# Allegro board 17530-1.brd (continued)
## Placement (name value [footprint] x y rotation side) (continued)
R6311  10KR2J-3-GP  [R402H16]  45.16 227.18 0 top
R6312  10KR2J-3-GP  [R402H16]  46.25 227.18 0 top
R6313  10KR2J-3-GP  [R402H16]  37.19 243.31 0 top
R6314  10KR2J-3-GP  [R402H16]  33.91 248.49 90 top
R6315  75KR2F-GP  [R402H16]  33.88 247.45 270 top
R6321  0R2J-2-GP  [R402H16]  62.84 230.4 270 top
R6402  10KR2J-3-GP  [R402H16]  150.82 144.07 90 top
R6403  10KR2J-3-GP  [R402H16]  171.63 135.51 270 top
R6404  10KR2J-3-GP  [R402H16]  171.63 136.52 270 top
R6406  10KR2J-3-GP  [R402H16]  150.82 142.98 270 top
R6407  10KR2J-3-GP  [R402H16]  171.33 134.01 0 top
R6408  10KR2J-3-GP  [R402H16]  170.31 134.01 0 top
R6409  220R6J-1-GP  [R1206H28]  9.22 233.3 90 top
R6410  4K7R2J-2-GP  [R402H16]  5.99 225.15 90 top
R6411  10KR2J-3-GP  [R402H16]  7.9 225.15 270 top
R6412  4K7R2J-2-GP  [R402H16]  5.89 231.67 90 top
R6413  330R6J-1-GP  [R1206H28]  9.22 231.09 90 top
R6414  10KR2J-3-GP  [R402H16]  5.87 230.56 270 top
R6415  10KR2J-3-GP  [R402H16]  164.41 154.15 0 top
R6416  10KR2J-3-GP  [R402H16]  27.56 260.6 90 top
R6417  4K7R2J-2-GP  [R402H16]  20.65 239.98 270 top
R6418  360R3-GP  [R603H22]  31.32 258.75 180 top
R6419  1KR2J-1-GP  [R402H16]  17.96 238.48 0 top
R6420  33R2J-2-GP  [R402H16]  19.02 238.48 180 top
R6421  10KR2J-3-GP  [R402H16]  25.07 258.52 0 top
R6801  0R2J-2-GP  [R402H16]  184.86 6.53 0 top
R6802  0R2J-2-GP  [R402H16]  184.94 4.62 0 top
R9101  0R3J-0-U-GP  [R603H22]  157.99 171.83 90 top
R9104  0R3J-0-U-GP  [R603H22]  158.75 168.53 180 top
R9105  33R2J-2-GP  [R402H16]  164.87 177.24 90 top
R9106  33R2J-2-GP  [R402H16]  169.16 171.45 180 top
R9107  33R2J-2-GP  [R402H16]  167.08 171.45 180 top
R9108  0R2J-2-GP  [R402H16]  168.15 171.45 180 top
R9110  10KR2J-3-GP  [R402H16]  165.86 165.35 270 top
R9111  0R2J-2-GP  [R402H16]  165.66 163.75 180 top
R9112  0R0402-PAD-2-GP  [0R0402-PAD-1]  165.2 168.25 0 top
R9113  0R2J-2-GP  [R402H16]  166.42 159.13 90 top
R9403  0R0603-PAD-2-GP-U  [0R0603-PAD-1-U]  175.77 50.16 180 top
R9901  0R0402-PAD-2-GP  [0R0402-PAD-1]  121.59 63.45 270 top
R9902  0R0402-PAD-2-GP  [0R0402-PAD-1]  121.59 62.41 270 top
R9903  1KR2J-1-GP  [R402H16]  176.81 172.43 90 top
R9904  1KR2J-1-GP  [R402H16]  122.07 56.36 90 top
R9905  0R2J-2-GP  [R402H16]  181 167.26 90 top
R9906  1KR2J-1-GP  [R402H16]  127 54.23 270 top
R9907  1KR2J-1-GP  [R402H16]  124.08 55.24 90 top
R9908  1KR2J-1-GP  [R402H16]  127 55.37 270 top
R9909  2K2R2J-2-GP  [R402H16]  127.69 61.16 270 top
R9910  1KR2J-1-GP  [R402H16]  127.13 62.36 270 top
R9911  0R2J-2-GP  [R402H16]  127.69 60.02 270 top
R9912  150R2F-1-GP  [R402H16]  129.29 55.5 180 top
R9913  1KR2J-1-GP  [R402H16]  124.08 56.39 90 top
R9916  0R0402-PAD-2-GP  [0R0402-PAD-1]  159.41 8.64 0 top
R9917  0R0402-PAD-2-GP  [0R0402-PAD-1]  178.56 34.92 0 top
R9918  0R0402-PAD-2-GP  [0R0402-PAD-1]  158.37 8.64 0 top
R9919  0R0402-PAD-2-GP  [0R0402-PAD-1]  168.52 152.77 90 top
R9920  0R0402-PAD-2-GP  [0R0402-PAD-1]  185.19 12.7 0 top
R9921  0R0402-PAD-2-GP  [0R0402-PAD-1]  170.89 94.13 90 top
R9922  10KR2J-3-GP  [R402H16]  26.09 255.32 90 top
R9923  2K2R2J-2-GP  [R402H16]  180.97 164.01 270 top
R9924  0R2J-2-GP  [R402H16]  34.57 171.75 90 top
R9928  10KR2J-3-GP  [R402H16]  164.11 150.62 180 top
R9929  0R2J-2-GP  [R402H16]  11.11 26.87 90 top
R9930  0R2J-2-GP  [R402H16]  18.38 8.64 270 top
R9931  680R2F-GP  [R402H16]  135.81 30.58 90 top
R9932  33R2J-2-GP  [R402H16]  169.78 109.85 315 top
R9933  22R2J-2-GP  [R402H16]  46.1 218.44 135 top
R9934  33R2J-2-GP  [R402H16]  170.68 111.68 315 top
R9935  22R2J-2-GP  [R402H16]  44.86 220.14 135 top
R9936  20KR2F-L-GP  [R402H16]  170.81 115.44 90 top
R9937  20KR2F-L-GP  [R402H16]  170.52 108.5 225 top
R9938  0R2J-2-GP  [R402H16]  35.31 221.36 180 bottom
R9939  0R2J-2-GP  [R402H16]  41.15 226.95 180 bottom
RJ45R1  SKT-RJ45-USB-87-GP  [RUA1JA-KJKC-DE0-0R]  109 19.62 0 top
RN1901  SRN10KJ-6-GP  [ARES8-CN24-MUH20]  160.83 150.19 180 top
RN2001  SRN10KJ-5-GP  [ARES2H18]  168.85 136.57 270 top
RN2401  SRN8K2J-4-GP  [ARES8-CN24H20]  162.43 34.47 0 top
RN2402  SRN8K2J-4-GP  [ARES8-CN24H20]  157.05 29.39 90 top
RN2403  SRN8K2J-4-GP  [ARES8-CN24H20]  157.3 23.27 90 top
RN2404  SRN1KJ-7-GP  [SMD-ARES4H18]  169.58 34.6 0 top
RN2405  SRN1KJ-7-GP  [SMD-ARES4H18]  167.58 34.6 0 top
RN2501  SRN33J-5-GP-U  [SMD-ARES4H18]  166.02 157.29 270 top
RN2502  SRN33J-5-GP-U  [SMD-ARES4H18]  176.13 170.79 90 top
RN5601  SRN2K2J-1-GP  [ARES2H16]  68.45 24.26 180 top
RN5901  SRN2K2J-1-GP  [ARES2H16]  45.85 20.75 270 top
SATA1  SKT-SATA7P-168-GP  [LE18077-Z55D-4F]  111.5 200.4 180 top
SATA2  SKT-SATA7P-29-GP-U  [ABA-SAT-010-K04-U]  176.5 178 180 top
SATA3  SKT-SATA7P-169-GP  [LE18077-Z55D-4F]  131.5 200.4 180 top
SATAP1  PIN-CONN6B-S1-GP  [733-71-06TB18]  94 201.65 0 top
SB1  CANON-LAKE-GP  [BGA874M250240H60]  152.3 123.5 90 top
SD1  SKT-SDCARD-61-GP  [WK21921-151146-7H]  41.97 272.3 180 top
SLOT1  PCISLT36-7-GP  [AAA-PCI-003-K45]  162.4 56.59 90 top
SLOT2  PCISLT164-95-GP  [2EGH8211-27DL-4F]  182.8 56.44 270 top
SSKT1  SKT-91960-0084L-GP  [SKT-SOIC8-1H211]  173.33 162.08 180 top
SSKT2  SKT-SPI16P-7-GP  [SKT-SOIC16-153139H258]  173.61 161.59 90 top
TC1101  E820U2D5VM-6-GP  [ECAP-100D6D3H375]  69.98 138.68 180 top
TC3201  E220U16VM-L8-GP  [ECAP-100D6D3H493]  124.33 9.78 180 top
TC3801  E220U16VM-L8-GP  [ECAP-100D6D3H493]  91.74 265.43 270 top
TC3901  E220U16VM-L8-GP  [ECAP-100D6D3H493]  87.63 20.83 270 top
TP401  TPAD28-2-GP  [TPAD28]  81.74 85.47 180 bottom
TP402  TPAD28-2-GP  [TPAD28]  82.91 86.57 180 bottom
TP403  TPAD28-2-GP  [TPAD28]  85.29 83.08 180 bottom
TP404  TPAD28-2-GP  [TPAD28]  80.97 77.89 180 bottom
TP405  TPAD28-2-GP  [TPAD28]  80.87 79.88 180 bottom
TP406  TPAD28-2-GP  [TPAD28]  80.67 82.07 180 bottom
TP407  TPAD28-2-GP  [TPAD28]  120.07 54.76 0 top
TP408  TPAD28-2-GP  [TPAD28]  78.47 79.4 180 bottom
TP409  TPAD28-2-GP  [TPAD28]  74.55 83.08 180 bottom
TP410  TPAD28-2-GP  [TPAD28]  76.76 79.78 180 bottom
TP411  TPAD28-2-GP  [TPAD28]  80.72 86.41 180 bottom
TP412  TPAD28-2-GP  [TPAD28]  79.28 78.26 180 bottom
TP413  TPAD28-2-GP  [TPAD28]  79.02 86.51 180 bottom
TP414  TPAD28-2-GP  [TPAD28]  76.96 82.17 180 bottom
TP415  TPAD28-2-GP  [TPAD28]  76.83 78.28 180 bottom
TP416  TPAD28-2-GP  [TPAD28]  77.6 87.2 180 bottom
TP417  TPAD28-2-GP  [TPAD28]  81.66 75.26 180 bottom
TP418  TPAD28-2-GP  [TPAD28]  80.67 76.23 180 bottom
TP419  TPAD28-2-GP  [TPAD28]  83.31 74.68 180 bottom
TP420  TPAD28-2-GP  [TPAD28]  82.83 75.97 180 bottom
TP421  TPAD28-2-GP  [TPAD28]  78.38 77.24 180 bottom
TP422  TPAD28-2-GP  [TPAD28]  79.22 76.12 180 bottom
TP601  TPAD28-2-GP  [TPAD28]  54.23 98.93 180 bottom
TP701  TPAD28-2-GP  [TPAD28]  82.55 80.26 180 bottom
TP903  TPAD28-2-GP  [TPAD28]  88.24 89.26 180 bottom
TP1501  TPAD28-2-GP  [TPAD28]  156.82 128.78 180 bottom
TP1504  TPAD28-2-GP  [TPAD28]  162.77 123.29 180 bottom
TP1505  TPAD28-2-GP  [TPAD28]  163.27 122.17 180 bottom
TP1506  TPAD28-2-GP  [TPAD28]  156.34 138.68 0 top
TP1507  TPAD28-2-GP  [TPAD28]  163.15 125.7 180 bottom
TP1508  TPAD28-2-GP  [TPAD28]  166.95 126.72 0 top
TP1509  TPAD28-2-GP  [TPAD28]  168.94 111.46 0 top
TP2001  TPAD28-2-GP  [TPAD28]  167.26 132.79 0 top
TP2002  TPAD28-2-GP  [TPAD28]  154.53 25.12 0 top
TP2003  TPAD28-2-GP  [TPAD28]  162.76 131.62 180 bottom
TP2101  TPAD28-2-GP  [TPAD28]  150.11 138.68 0 top
TP2102  TPAD28-2-GP  [TPAD28]  149.99 139.95 0 top
TP2501  TPAD28-2-GP  [TPAD28]  46.25 260.15 0 top
TP2502  TPAD28-2-GP  [TPAD28]  47.75 260.12 0 top
TP3101  -  [TPAD30]  124.49 32.36 0 top
TP3102  -  [TPAD30]  122.38 32.38 0 top
TP3103  -  [TPAD30]  120.22 32.33 0 top
TP9106  -  [TPAD30]  157.61 176.28 0 bottom
TP9901  TPAD28-2-GP  [TPAD28]  159.56 6.35 0 top
TP9902  TPAD28-2-GP  [TPAD28]  178.54 33.15 0 top
TP9903  TPAD28-2-GP  [TPAD28]  158.37 6.65 0 top
TP9904  TPAD28-2-GP  [TPAD28]  168.83 152.65 90 bottom
TP9905  TPAD28-2-GP  [TPAD28]  185.7 11.13 0 top
TP9906  TPAD28-2-GP  [TPAD28]  170.69 92.58 90 top
TR3201  FILTER-4P-156-GP-U  [L125100-4PH24]  127.29 32.15 90 top
TR3202  FILTER-4P-156-GP-U  [L125100-4PH24]  127.29 29.07 90 top
TR3801  FILTER-4P-156-GP-U  [L125100-4PH24]  94.98 261.36 315 top
TR3802  FILTER-4P-156-GP-U  [L125100-4PH24]  96.59 259.75 315 top
TR3901  FILTER-4P-156-GP-U  [L125100-4PH24]  95.01 23.81 180 top
TR3902  FILTER-4P-156-GP-U  [L125100-4PH24]  92.85 23.79 180 top
TR5601  FILTER-4P-156-GP-U  [L125100-4PH24]  78.61 19.43 0 top
TR5602  FILTER-4P-156-GP-U  [L125100-4PH24]  76.45 19.43 0 top
TR5603  FILTER-4P-156-GP-U  [L125100-4PH24]  74.17 19.43 0 top
TR5604  FILTER-4P-156-GP-U  [L125100-4PH24]  71.88 19.43 0 top
U401  MMDT3904-2-GP  [SOT-363-1H44]  20.95 173.23 0 top
U2401  SCH5553-NU-GP  [PFPCC128-5H48]  170.89 22.38 180 top
U2405  TC7SZ32FU-2-GP  [SC70-5H44]  32 172.52 0 top
U2501  MX25L25673GM2I-08G-GP  [SOIC8-1H86]  173.33 162.08 0 top
U2502  MX25L25673GMI-10G-GP  [SOIC16-6H105]  173.61 161.59 270 top
U2601  G709T1UF-GP  [SOT-23-5H56]  179.55 6.58 0 top
U2602  SNLVC1G08DCKRG4-GP  [SC70-5H44]  176.1 6.96 0 top
U2701  ALC3820-CG-GP  [LQFP48H63]  66.42 258.83 180 top
U3101  RTL8111G-CGT-1-GP-U2  [QFN32J4-G2D85H36]  138.05 24 90 top
U3201  G524B1T11U-GP  [SOT-23-5H58]  126.72 16.03 0 top
U3301  RTS5170-GR-GP  [QFN24-G2D5H40-U]  38.73 259.08 180 top
U3801  G524B1T11U-GP  [SOT-23-5H58]  86.87 260.1 180 top
U3901  G524B1T11U-GP  [SOT-23-5H58]  89.13 28.07 0 top
U4002  2N7002KDW-1-GP  [SOT-363H44]  100.58 28.7 90 top
U4003  2N7002K-2-GP  [SOT23DGS2D4H44]  104.27 30.23 0 top
U4009  SNLVC1G08DCKRG4-GP  [SC70-5H44]  112.39 33.53 270 top
U4010  SNLVC1G08DCKRG4-GP  [SC70-5H44]  26.8 172.97 180 top
U4201  AOZ2331DI-1-GP  [SON14J3020-G2610H32]  6.96 219.33 0 top
U4202  2N7002KDW-1-GP  [SOT-363H44]  44.53 193.32 90 top
U4204  TPCC8103-GP  [PPAK-8P-3333-2H36]  183.9 193.68 0 top
U4801  2N7002KDW-1-GP  [SOT-363H44]  154.89 189.87 0 top
U5601  2N7002KDW-1-GP  [SOT-363H44]  68.83 20.6 0 top
U5602  AP2331SA-7-GP  [SOT23-2D4-312H48]  65.02 24.79 0 top
U5901  RTD2166-CGT-GP  [QFN32J4-G2D85H36]  56.39 19.56 270 top
U6301  RT9724GB-GP  [SOT-23-5H51]  36.98 233.09 0 top
U6302  2N7002K-2-GP  [SOT23DGS2D4H44]  34.82 245.03 0 top
U6303  2N7002K-2-GP  [SOT23DGS2D4H44]  67.06 233.81 90 top
U6401  2N7002KDW-1-GP  [SOT-363H44]  28.07 263.27 180 top
U6402  2N7002KDW-1-GP  [SOT-363H44]  27.23 257.76 0 top
U9101  NPCT750JAAYX-GP  [QFN32G5-G3D6H32]  162.94 173.1 90 top
UC3201  SCD01U50V2KX-1DLGP  [C402H22]  122.33 16.41 0 top
UC3202  SCD1U16V2KX-3DLGP  [C402H22]  123.22 16.41 0 top
UC3203  SCD1U16V2KX-3DLGP  [C402H22]  124.18 15.39 180 top
UC3801  SCD1U16V2KX-3DLGP  [C402H22]  87.38 262.89 270 top
UC3901  SCD1U16V2KX-3DLGP  [C402H22]  88.6 25.32 90 top
USB2R1  SKT-USB12-24-GP  [SKT-USB12-157183]  88 9.19 0 top
USB3F1  SKT-USB11-153-GP  [SKT-USB11-138166]  85.22 274.75 180 top
USB3F2  SKT-USB11-153-GP  [SKT-USB11-138166]  107.22 274.75 180 top
VGA1  D-SUB-15-295-GP  [VDS075W-D307-00A3F2B]  37 3.9 0 top
X1801  XTAL-24MHZ-182-GP  [OSC-3225-4P-3H36]  147.07 102.82 270 top
X1802  XTAL-32D768KHZ-88-GP  [SMD49-3215-0713H36]  169.8 149.22 0 top
X3101  XTAL-25MHZ-202-GP  [SMD-OSC38H20]  137.67 32.59 180 top

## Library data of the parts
ATX1 = W4202VT-203P-D: tolerance: 020.80369.0006
ATX2 = HM3502E-P1: tolerance: 20.81163.004
AUD1 = ABA-JAK-028-K03: tolerance: 22.10251.831
BT2501 = 20-00950-1A01-A-U: tolerance: 022.70019.0001
C402 C403 C803 C806 C1103 C1104 C1108 = C402H22: tolerance: 78.10421.L0L
C601 C603 C805 C807 C808 C1101 C1102 C1105 C1106 C1109 C1201 C1202 C1205-C1208 C1210 C1212 C2101 C2102 C2104-C2107 C2113-C2117 C2406 C2408 C2415-C2423 C2425 C2704 C2707 C2708 C2712 C2714 C2716-C2718 C2721 C3101 C3103 C3105-C3108 C3111 C3113 C3301 C3307 C3806 C3807 C4007 C4008 C4010 C4011 C4212 C4218 C4220 C4222 C4225 C4301 C4302 C5101 C5902-C5906 C5908-C5915 C6203 C6205 C6213 C6215 C6301-C6304 C6309 C6310 C6402 C6403 C9102 C9103 C9105 C9106 C9310-C9312 C9403-C9405 C9410 C9901-C9905 C9907-C9911 PC4803 PC4810 PC4913 PC5205 UC3202 UC3203 UC3801 UC3901 = C402H22: tolerance: 78.10421.2FLDL
C602 C1209 = C402H22: tolerance: 78.22321.2FLDL
C801 C1033 C1203 C2006 C2007 C2103 C2110 C2120-C2125 C2128 C2405 C2412 C2501 C3112 C3201 C3303 C3304 C3805 C3901 C4009 C4012 C4013 C4203 C4204 C4224 C4226 C4227 C6201 C6404 = C402H22: tolerance: 78.10523.5FLDL
C802 C4209 C4210 C5609 PC4407 PC4408 PC4410 PC4412 PC4420 PC4421 PC4428 PC4429 = C402H22: tolerance: 78.10422.5FLDL
C804 C2703 C2705 C2709-C2711 C2901 C3001 C3002 C3007 C3008 C4208 C6013 C6014 C6206 C6214 PC4501 PC4502 PC4506 PC4507 PC4511 PC4512 PC4516 PC4517 PC4601 PC4602 PC4606 PC4607 PC4702 PC4703 PC4901-PC4905 PC5004-PC5007 PC5102-PC5105 = C805H58: tolerance: 78.10622.51LDL
C1025-C1027 PC1004-PC1006 PC1019-PC1023 = C805H58: tolerance: 78.22610.L2L
C1028-C1031 PC1050-PC1053 = C805H54: tolerance: 78.47610.51LDL
C1032 C2722 PC1007-PC1012 PC1018 PC1034-PC1045 PC1058 PC4808 PC4809 = C805H54: tolerance: 78.22610.51LDL
C1107 C1204 C1211 C2108 C2109 C2411 C2414 C3102 C3104 C3114 C3302 C5907 = C603H36: tolerance: 78.47520.5BLDL
C1110 C1213 = C402H22: tolerance: 78.22510.5FLDL
C1801-C1804 = C402H22: tolerance: 78.15034.1FLDL
C2111 C2112 C2118 C2119 C2127 C2129 C6308 PC1001 PC1002 PC1046-PC1049 = C603H40: tolerance: 78.22610.5BLDL
C2126 C2424 C2706 C2713 C3117 C3306 C4205 C4206 C6307 C9101 C9104 C9411 = C603H36: tolerance: 78.10610.5BLDL
C2401 C2403 C2413 C2427 C2903 C2906 C2907 C3003-C3006 C3009 C3010 = C402H22: tolerance: 78.10134.1FLDL
C2402 C2404 PC4405 PC4418 PC4812 = C402H22: tolerance: 78.22224.2FLDL
C2407 C2426 PC4403 PC4806 UC3201 = C402H22: tolerance: 78.10324.2FLDL
C2701 C2702 C5901 PC4402 = C603H36: tolerance: 78.22523.5BLDL
C2715 C5916-C5921 PC4914 PC4915 = C402H22: tolerance: 78.22034.1FLDL
C2719 C2720 PC4503 PC4508 PC4513 PC4518 PC4603 PC4608 PC4704 PC4906-PC4908 PC5008 PC5106 = C603H35: tolerance: 78.10424.2BLDL
C2902 C4207 C4211 = C805H56: tolerance: 78.10622.LAL
C2904 C2905 = C805H54: tolerance: 78.47522.51LDL
C3109 = C402H22: tolerance: 78.10421.2FLDL; signal model: Graser_C3109
C3110 = C402H22: tolerance: 78.10421.2FLDL; signal model: Graser_C3110
C3115 = C402H22: tolerance: 78.10421.2FLDL; signal model: Graser_C3115
C3116 = C402H22: tolerance: 78.10421.2FLDL; signal model: Graser_C3116
C3118 C3119 = C402H22: tolerance: 78.20034.1FLDL
C3305 = C402H22: tolerance: 78.6R874.1FLDL
C3801 = C402H22: tolerance: 78.10421.2FLDL; signal model: Graser_C3801
C3802 = C402H22: tolerance: 78.10421.2FLDL; signal model: Graser_C3802
C3803 = C402H22: tolerance: 78.10421.2FLDL; signal model: Graser_C3803
C3804 = C402H22: tolerance: 78.10421.2FLDL; signal model: Graser_C3804
C4201 C4202 PC4409 PC4416 PC4422 PC4427 PC4807 PC4911 PC4912 = C402H22: tolerance: 78.10224.2FLDL
C4219 = C402H22: tolerance: 78.10324.L0L
C4221 C4223 = C603H40: tolerance: 078.22522.05BD
C4303 C4304 PC4401 PC4504 PC4509 PC4514 PC4519 PC4604 PC4609 PC4701 PC4705 PC4706 PC4804 PC4909 PC4910 PC4916 PC4917 PC5001-PC5003 PC5010 PC5101 PC5107 PC5109 PC5202 = C603H36: tolerance: 078.10524.05BD
C5601 = C402H22: tolerance: 78.10421.2FLDL; signal model: Graser_C5601
C5602 = C402H22: tolerance: 78.10421.2FLDL; signal model: Graser_C5602
C5603 = C402H22: tolerance: 78.10421.2FLDL; signal model: Graser_C5603
C5604 = C402H22: tolerance: 78.10421.2FLDL; signal model: Graser_C5604
C5605 = C402H22: tolerance: 78.10421.2FLDL; signal model: Graser_C5605
C5606 = C402H22: tolerance: 78.10421.2FLDL; signal model: Graser_C5606
C5607 = C402H22: tolerance: 78.10421.2FLDL; signal model: Graser_C5607
C5608 = C402H22: tolerance: 78.10421.2FLDL; signal model: Graser_C5608
C5610 C5611 PC4404 PC4414 PC4417 PC4426 = C402H22: tolerance: 78.47124.2FLDL
C5922 C5923 = C402H22: tolerance: 078.2R074.01FD
C6001 = C402H22: tolerance: 78.10324.2FLDL; signal model: Graser_C6001
C6002 = C402H22: tolerance: 78.10324.2FLDL; signal model: Graser_C6002
C6003 = C402H22: tolerance: 78.10324.2FLDL; signal model: Graser_C6003
C6004 = C402H22: tolerance: 78.10324.2FLDL; signal model: Graser_C6004
C6005 = C402H22: tolerance: 78.10324.2FLDL; signal model: Graser_C6005
C6006 = C402H22: tolerance: 78.10324.2FLDL; signal model: Graser_C6006
C6007 = C402H22: tolerance: 78.10324.2FLDL; signal model: Graser_C6007
C6008 = C402H22: tolerance: 78.10324.2FLDL; signal model: Graser_C6008
C6009 = C402H22: tolerance: 78.10324.2FLDL; signal model: Graser_C6009
C6010 = C402H22: tolerance: 78.10324.2FLDL; signal model: Graser_C6010
C6011 = C402H22: tolerance: 78.10324.2FLDL; signal model: Graser_C6011
C6012 = C402H22: tolerance: 78.10324.2FLDL; signal model: Graser_C6012
C6209 = C402H22: tolerance: 078.22423.05FD; signal model: Graser_C6209
C6210 = C402H22: tolerance: 078.22423.05FD; signal model: Graser_C6210
C6211 = C402H22: tolerance: 078.22423.05FD; signal model: Graser_C6211
C6212 = C402H22: tolerance: 078.22423.05FD; signal model: Graser_C6212
C6305 = C402H22: tolerance: 78.10421.2FLDL; signal model: Graser_C6305
C6306 = C402H22: tolerance: 78.10421.2FLDL; signal model: Graser_C6306
C9301 = C402H22: tolerance: 078.22423.05FD; signal model: Graser_C9301
C9302 = C402H22: tolerance: 078.22423.05FD; signal model: Graser_C9302
C9303 = C402H22: tolerance: 078.22423.05FD; signal model: Graser_C9303
C9304 = C402H22: tolerance: 078.22423.05FD; signal model: Graser_C9304
C9305 = C402H22: tolerance: 078.22423.05FD; signal model: Graser_C9305
C9306 = C402H22: tolerance: 078.22423.05FD; signal model: Graser_C9306
C9307 = C402H22: tolerance: 078.22423.05FD; signal model: Graser_C9307
C9308 = C402H22: tolerance: 078.22423.05FD; signal model: Graser_C9308
C9309 = C402H22: tolerance: 078.22423.05FD; signal model: Graser_C9309
C9313 = C402H22: tolerance: 078.22423.05FD; signal model: Graser_C9313
C9314 = C402H22: tolerance: 078.22423.05FD; signal model: Graser_C9314
C9315 = C402H22: tolerance: 078.22423.05FD; signal model: Graser_C9315
C9316 = C402H22: tolerance: 078.22423.05FD; signal model: Graser_C9316
C9317 = C402H22: tolerance: 078.22423.05FD; signal model: Graser_C9317
C9318 = C402H22: tolerance: 078.22423.05FD; signal model: Graser_C9318
C9319 = C402H22: tolerance: 078.22423.05FD; signal model: Graser_C9319
C9320 = C402H22: tolerance: 078.22423.05FD; signal model: Graser_C9320
C9321 = C402H22: tolerance: 078.22423.05FD; signal model: Graser_C9321
C9322 = C402H22: tolerance: 078.22423.05FD; signal model: Graser_C9322
C9323 = C402H22: tolerance: 078.22423.05FD; signal model: Graser_C9323
C9324 = C402H22: tolerance: 078.22423.05FD; signal model: Graser_C9324
C9325 = C402H22: tolerance: 078.22423.05FD; signal model: Graser_C9325
C9326 = C402H22: tolerance: 078.22423.05FD; signal model: Graser_C9326
C9328 = C402H22: tolerance: 078.22423.05FD; signal model: Graser_C9328
C9329 = C402H22: tolerance: 078.22423.05FD; signal model: Graser_C9329
C9331 = C402H22: tolerance: 078.22423.05FD; signal model: Graser_C9331
C9332 = C402H22: tolerance: 078.22423.05FD; signal model: Graser_C9332
C9334 = C402H22: tolerance: 078.22423.05FD; signal model: Graser_C9334
C9335 = C402H22: tolerance: 078.22423.05FD; signal model: Graser_C9335
C9336 = C402H22: tolerance: 078.22423.05FD; signal model: Graser_C9336
C9337 = C402H22: tolerance: 078.22423.05FD; signal model: Graser_C9337
C9338 = C402H22: tolerance: 078.22423.05FD; signal model: Graser_C9338
C9401 = C402H22: tolerance: 078.22423.05FD; signal model: Graser_C9401
C9402 = C402H22: tolerance: 078.22423.05FD; signal model: Graser_C9402
CPU1 = SKTBGA1151R754612-UH369: tolerance: 062.10015.0161
D2501 D2601 D2602 D5601 D6301 D6302 = SOD323AKH38: tolerance: 83.R5003.H8H
D2502 = SOT-23-9H44: tolerance: 75.00054.A7D
D2701 = SOD-523-4H28: tolerance: 75.05125.070
D2901 = SOT23-2D4-123H44: tolerance: 075.00054.0A7D
D4301 D4302 = D5126145AKH91: tolerance: 83.P4SSM.EAM
DB2001 DB2002 R803 R2102 R6309 R9101 R9104 = R603H22: tolerance: 63.00000.00L
DIMM1 DIMM2 = AH08847-A9L2-4M: tolerance: 022.10010.0761
EU3201-EU3204 EU3803 EU3901 = SOT-6-1H58: tolerance: 075.00199.007C
EU3801 EU3802 EU5601-EU5603 = DFN10G2510H26: tolerance: 75.01045.073
EU5901 EU5902 = SOT-6H58: tolerance: 075.02304.0C7C
F3301 = POLYSW-2114H30: tolerance: 069.50001.0031
F5901 = POLYSW-2114H30: tolerance: 69.48001.081
FANC1 = P254-1104A0ADKP-W: tolerance: 021.60305.0104
FANS1 = HF2704F-RM1: tolerance: 021.60234.0104
FL2901-FL2903 L3001-L3006 = L402H24: tolerance: 68.00213.031
HDMI1 = SKT-HDMI23-150122-9-U: tolerance: 62.10078.641
HPMIC1 = C35012W-L101-39AA00R: tolerance: 022.10002.0A81
HS1901 HS1902 = HB9603E-DW: tolerance: 21.60564.102
HS2601 HS2604 = GEN330R190-8-F-C: tolerance: ZZ.AFEN8.190
HS2602 HS2603 HS2605 HS2606 = GEN315R158-8-F-C-S-U: tolerance: ZZ.SCREW.541
HS6301 = STF256R109H99: tolerance: 34.3NH01.001
JMP1 = 21S-92-03GB16: tolerance: 021.60308.0203
L2101 L2102 = L603H38: tolerance: 68.00230.131
L2701-L2703 = L603H38: tolerance: 68.00335.181
L5901 L5902 = L603H38: tolerance: 68.00335.101
L5903-L5905 = L1608-UH38: tolerance: 68.00084.B61
LED1 = LED1608AKH28: tolerance: 83.19213.H70
LPC1 = 87212-1400N: tolerance: 20.F0765.014
NGFF1 = AS0BC21-S40BE-7H: tolerance: 062.10003.0611
NGFF2 = AS0BC21-S85BM-7H: tolerance: 062.10003.0601
PC4406 PC4419 = C402H22: tolerance: 78.33034.1FLDL
PC4411 PC4423 = C402H22: tolerance: 78.33224.2FLDL
PC4413 = C402H22: tolerance: 78.22124.2FLDL
PC4415 PC4425 PC4505 PC4510 PC4515 PC4520 PC4605 PC4610 PC4707 PC5014 PC5110 = C402H22: tolerance: 78.15224.2FLDL
PC4424 = C402H22: tolerance: 78.33124.2FLDL
PC4708 PC5013 PC5108 = C402H22: tolerance: 78.18034.1FLDL
PC4801 PC4802 PC5009 PC5011 PC5012 PC5201 PC5203 PC5204 = C805H50: tolerance: 78.10623.51LDL
PC4805 PC4811 PC5015 = C402H22: tolerance: 078.47322.02FD
PC4918 PC4919 = C402H22: tolerance: 078.22423.05FD
PC5206 = C402H22: tolerance: 78.15134.1FL
PG4501-PG4508 PG4601-PG4604 PG4701 PG4901 PG4902 PG5005 PG5006 PR4701-PR4706 PR4801-PR4807 PR4809 PR4901-PR4906 PR4908 PR4910 PR4912 PR4914 PR4916 PR4918 PR4920 PR4922 PR4924 PR4925 PR4927 PR4929 PR4933 PR4934 PR4936-PR4940 PR4945-PR4949 PR5006 PR5008 PR5010-PR5013 PR5015 PR5017 PR5018 PR5020-PR5023 PR5026-PR5030 PR5117-PR5135 = GAP-CLOSE-PWR-3: tolerance: ZZ.CLOSE.001
PG4903 = GAP-CLOSE-PWR-2U: tolerance: ZZ.0TPAD.011
PL4501-PL4504 PL4601 PL4602 = RT-D6D3-1D4-103065H394: tolerance: 019.40016.0211
PL4701 = L7066-1830-UH119: tolerance: 68.R4710.10M
PL4901 PL4902 = RT-D6D6-6D6-108108H426: tolerance: 019.40027.0011
PL4903-PL4905 PL5002 PL5003 PL5104 PL5105 = L805H44: tolerance: 68.00335.111
PL5001 = RT-D6D4-1D9-103072H394: tolerance: 019.40016.0191
PL5101 = L115100-2030H158: tolerance: 68.1R51A.10E
PR4401 = R603H22: tolerance: 64.2R205.55L
PR4402 PR4409 PR4442 R404 R1103 R1106 R1203 R1206 R3103 = R402H16: tolerance: 64.10015.6DL
PR4403 = R402H16: tolerance: 64.26125.6DL
PR4404 PR4416 PR4423 PR4445 PR4454 R402 R403 R1513 R2024 R2605 R2614 = R402H14: tolerance: 64.10005.6DL
PR4405 = R402H16: tolerance: 64.45R35.6DL
PR4406 R3001 R3002 R3005 R3006 R3013 R3014 R5913-R5915 = R402H16: tolerance: 64.75R05.6DL
PR4407 PR4439 R5916 R5917 = R402H16: tolerance: 64.47R05.6DL
PR4408 PR4440 = R402H16: tolerance: 64.40215.6DL
PR4410 PR4435-PR4438 PR4459 PR4460 PR4715 PR4717 PR4808 PR4813 PR4815 R2905 R2906 = R402H14: tolerance: 64.10R05.6DL
PR4411 R418 R802 = R402H16: tolerance: 64.49R95.6DL
PR4412 PR4415 PR4419 PR4422 PR4426 PR4427 PR4429 PR4432 PR4434 PR4443 PR4446 PR4451 PR4960 R2706 R2707 R2709 R2711 = R402H16: tolerance: 64.10035.6DL
PR4413 PR4424 PR4441 PR4716 PR4956 PR4957 PR5116 PR5202 PR5206 R2411 R2413 R5918 = R402H16: tolerance: 64.10025.6DL
PR4414 PR4417 PR4421 PR4425 PR4444 PR4448 = R402H16: tolerance: 64.69815.6DL
PR4418 PR4447 PR4812 PR5019 PR5204 R407 R408 R410-R412 R417 R801 R809 R902 R903 R1105 R1205 R1701 R1702 R1816 R1818 R1822 R2034 R2036 R2039 R2422 R2426 R2434 R2438 R2439 R3102 R3813 R4006-R4010 R4013 R4015 R4019 R4021 R4024 R4025 R4201 R4202 R4302 R5003 R5101 R5911 R5912 R6201 R9112 R9901 R9902 R9916-R9921 = 0R0402-PAD-1: tolerance: ZZ.00PAD.M11
PR4420 = R402H16: tolerance: 64.30015.6DL
PR4428 = R402H16: tolerance: 64.27035.6DL
PR4430 R2403 R2405 R2412 R2465 R2469 R2470 R2473 = R402H16: tolerance: 64.30025.6DL
PR4431 PR4455 PR4466 PR4468 = NTC-402H24-U: tolerance: 69.60028.041
PR4433 = R402H16: tolerance: 64.35725.6DL
PR4449 PR4453 = R603: tolerance: 64.68125.55L
PR4450 = R402H16: tolerance: 64.36015.6DL
PR4452 = R402H16: tolerance: 64.26135.6DL
PR4456 = R402H16: tolerance: 64.13335.6DL
PR4457 = R402H16: tolerance: 64.24925.6DL
PR4458 = R402H16: tolerance: 64.42225.6DL
PR4461 = R402H16: tolerance: 64.75R05.6DL; signal model: Graser_PR4461
PR4462 R2415 R2416 = R402H16: tolerance: 64.20015.6DL
PR4463 PR4464 R2009 R2010 = R402H16: tolerance: 64.49905.6DL
PR4465 = R402H16: tolerance: 64.47525.6DL
PR4467 PR4469 = R402H16: tolerance: 64.38325.6DL
PR4471 PR5025 R2466 R5609 R9936 R9937 = R402H16: tolerance: 64.20025.6DL
PR4501 PR4505 PR4507 PR4511 PR4514 PR4517 PR4520 PR4523 PR4525-PR4528 PR4601 PR4605 PR4608 PR4611 PR4613 PR4614 = R805H24: tolerance: 64.2R205.16L
PR4503 PR4509 PR4515 PR4521 PR4603 PR4609 PR4710 PR4959 PR4961 PR5004 PR5107 PR5109 R413 R416 R422 R805 R1502 R1506 R1509 R1510 R1601 R1604-R1607 R1610 R1704-R1706 R1709 R1712-R1714 R1801 R1803 R1805-R1807 R1809 R1902 R1905 R1910-R1912 R1917-R1919 R2001 R2002 R2007 R2015 R2041 R2044 R2303 R2305 R2312 R2314 R2419 R2421 R2425 R2427 R2430 R2432 R2435 R2448 R2449 R2452 R2453 R2462-R2464 R2476-R2478 R2701 R2716 R2717 R3811 R3812 R3814 R3815 R3817 R4001 R4020 R4022 R4204 R4207 R4220 R4222 R4801 R4803 R6304 R6306 R6308 R6311-R6314 R6402-R6404 R6406-R6408 R6411 R6414-R6416 R6421 R9110 R9922 R9928 = R402H16: tolerance: 63.10334.1DL
PR4504 PR4510 PR4516 PR4522 PR4604 PR4610 = R805H24: tolerance: 63.1R031.16L
PR4506 PR4512 PR4518 PR4524 PR4606 PR4612 R415 R427 R2011 R2026 R2028 = R402H16: tolerance: 64.51R05.6DL
PR4707 PR4709 PR4712 PR4713 PR4932 PR4941-PR4944 PR4950 PR4951 PR5005 PR5007 PR5016 PR5108 PR5110 PR5113 PR5115 = R805H24: tolerance: 63.2R231.16L
PR4708 = R402H16: tolerance: 64.40225.6DL
PR4711 PR5112 = R402H16: tolerance: 64.47035.6DL
PR4714 PR5114 = R402H16: tolerance: 64.48715.6DL
PR4810 = R805H24: tolerance: 63.10133.16L
PR4811 = R402H16: tolerance: 64.22015.6DL
PR4814 = R402H16: tolerance: 64.47015.6DL
PR4816 = R402H16: tolerance: 64.24025.6DL
PR4952 = R402H16: tolerance: 64.78725.6DL
PR4953 = R402H16: tolerance: 64.62025.6DL
PR4954 = R402H16: tolerance: 64.66515.6DL
PR4955 = R402H16: tolerance: 64.15425.6DL
PR4958 R414 R806 R807 R810 R1515 R1516 R2045-R2048 R2052-R2055 R2406 R2410 R2467 R2475 R2619 R4206 R5910 R5919 = R402H16: tolerance: 63.10434.1DL
PR4962 = R402H16: tolerance: 64.28025.6DL
PR5001 = R402H16: tolerance: 64.2R205.6DL
PR5002 R2101 R2503 R2705 R2708 R3105 R9403 = 0R0603-PAD-1-U: tolerance: ZZ.00PAD.M21
PR5003 = R402H16: tolerance: 64.20535.6DL
PR5009 = R402H16: tolerance: 64.62035.6DL
PR5014 PR5201 PR5203 = 0R0805-PAD-1-U: tolerance: ZZ.00PAD.M31
PR5024 = R402H16: tolerance: 64.15825.6DL
PR5111 = R402H16: tolerance: 64.56025.6DL
PR5205 = R402H16: tolerance: 64.21525.6DL
PT4501 PT4504 PT4506 PT4601 PT4901 = ECAP-138D8-UH355: tolerance: 09.2771D.C8L
PT4502 PT4503 PT4505 PT4507 PT4508 PT4602-PT4605 PT4701 PT4702 PT4801 PT5001 PT5101 TC1101 = ECAP-100D6D3H375: tolerance: 09.8271V.08L
PT4902 PT4903 = SE3116H241: tolerance: 79.22710.30L
PU4401 = QFN52J6-G4D8-UH40: tolerance: 074.81220.0D73
PU4501 PU4505 PU4509 PU4513 PU4601 PU4604 PU4802 PU4901 PU4903 PU5002 Q4201 = PPAK-8P-5262H40: tolerance: 084.36358.0037
PU4502 PU4506 PU4510 PU4514 PU4602 PU4605 = DFN8G2-G1309-UH40: tolerance: 074.81258.00E3
PU4503 PU4504 PU4507 PU4508 PU4511 PU4512 PU4515 PU4516 PU4603 PU4606 PU4904 PU4905 PU5003 = PPAK-8P-5262H40: tolerance: 084.36356.0037
PU4701 PU5101 = DFN10G3-G265175H32: tolerance: 74.08237.B73
PU4702 PU5102 = PPAK-8P-G5324H44-COLAY: tolerance: ZZ.00215.037
PU4801 = SOT-6H58: tolerance: 74.05611.03P
PU4902 = QFN20-G1D75H32: tolerance: 074.06575.0A43
PU5001 = QFN20-G1D75H32: tolerance: 074.08231.0073
PU5201 = SOIC8-G3530H63: tolerance: 74.05930.B3D
PWRSW1 = A2003WV0-2LX4PA-6T-Z-U: tolerance: 21.62977.204
Q801 Q5901 = SOT23DGS2D8H50: tolerance: 84.03418.A31
Q802 Q5601 Q6401 Q9103 U4002 U4202 U4801 U5601 U6401 U6402 = SOT-363H44: tolerance: 75.27002.F7C
Q2001 Q2701-Q2704 = SOT23CBE2D4H44: tolerance: 84.T3906.E11
Q2401 Q2402 Q2405 Q2406 Q2408 Q2901 Q3001 Q4002 U401 = SOT-363-1H44: tolerance: 75.03904.D7C
Q2403 Q2404 Q2409 Q4205 Q4207 Q9102 = SOT23CBE2D4H44: tolerance: 84.T3904.H11
Q2407 Q9101 U4003 U6302 U6303 = SOT23DGS2D4H44: tolerance: 84.2N702.J31
Q3801 = SOT-363H44: tolerance: 75.03904.A7C
Q4206 = SOT23DGS2D4H48: tolerance: 84.02130.031
R301 R602 R701 R1207 = R402H16: tolerance: 64.24R95.6DL
R401 = R402H16: tolerance: 64.56R25.6DL
R405 = R402H16: tolerance: 64.22005.6DL
R409 = R402H16: tolerance: 64.49905.6DL; signal model: Graser_R409
R419 = R402H16: tolerance: 64.60415.6DL
R420 = R402H16: tolerance: 64.28015.6DL
R421 = R402H16: tolerance: 64.20R05.6DL; signal model: Graser_R421
R423 R2021 R2504 = R402H16: tolerance: 64.15015.6DL
R424-R426 R1611 R1703 R1708 R2003 R2012-R2014 R2037 R2038 R2318 R2325 R2450 R2501 R2502 R2506 R2718 R2719 R2902 R2908 R2910 R3008 R3010 R4023 R6419 R9903 R9904 R9906-R9908 R9910 R9913 = R402H16: tolerance: 63.10234.1DL
R601 R1204 = R402H16: tolerance: 64.2R005.6DL
R702 = R402H16: tolerance: 63.20034.1DL
R804 R1511 R2474 R2702 R4203 R4802 = R402H16: tolerance: 63.47334.1DL
R808 R2035 R2043 R2301 R2302 R2307 R2326 R2328 R2431 R2601 R2615 R2704 R2903 R2904 R3807 R3808 R4205 R4301 R5901-R5909 R6410 R6412 R6417 = R402H16: tolerance: 63.47234.1DL
R901 = R402H16: tolerance: 64.20R05.6DL; signal model: Graser_R901
R1101 R1201 = R402H16: tolerance: 64.24005.6DL
R1102 R1202 R2004 R2306 R2612 R2715 R3809 R3810 R3818 R5001 R5002 R6202 R6203 R6303 R6321 R6801 R6802 R9108 R9111 R9113 R9905 R9911 R9924 R9929 R9930 R9938 R9939 = R402H16: tolerance: 63.R0034.1DL
R1104 R5601-R5608 = R402H16: tolerance: 63.47134.1DL
R1503 R1508 R1901 R2402 R2604 R2617 R4017 R4018 = R402H16: tolerance: 64.82015.6DL
R1504 R1913 R2017 R2019 R2020 R2022 R2032 R2033 R2433 R2703 R6420 R9105-R9107 R9932 R9934 = R402H16: tolerance: 63.33034.1DL
R1507 R5610 = R402H16: tolerance: 63.10534.1DL
R1512 R9912 = R402H16: tolerance: 64.15005.6DL
R1514 = R402H16: tolerance: 64.20005.6DL
R1609 = R402H16: tolerance: 64.11305.6DL
R1710 = R402H16: tolerance: 64.61905.6DL; signal model: Graser_R1710
R1711 = R402H16: tolerance: 63.30034.1DL; signal model: Graser_R1711
R1802 = R402H16: tolerance: 64.60R45.6DL
R1812 R2710 R2712 = R402H16: tolerance: 64.20035.6DL
R1814 = R603H22: tolerance: 63.10633.15L
R1906-R1908 R2005 R2324 R2327 R2329 R2603 R2616 R2901 R3011 R3012 R9909 R9923 = R402H16: tolerance: 63.22234.1DL
R1914-R1916 R2401 R2407 R9933 R9935 = R402H16: tolerance: 63.22034.1DL
R2006 = 0R0402-PAD-1: tolerance: ZZ.00PAD.M11; signal model: Graser_R2006
R2025 R2027 = R402H16: tolerance: 63.30034.1DL
R2040 R2042 = R402H16: tolerance: 64.30125.6DL
R2201 = R402H16: tolerance: 64.30R15.6DL; signal model: Graser_R2201
R2304 R2309 R2310 R2313 R2317 R2323 R2442 R2602 R2618 R4003 = R402H16: tolerance: 63.20334.1DL
R2404 R2414 R2417 = R402H16: tolerance: 64.91015.6DL
R2408 R9931 = R402H16: tolerance: 64.68005.6DL
R2409 R2472 = R402H16: tolerance: 64.68015.6DL
R2423 = R402H16: tolerance: 64.71515.6DL
R2424 = R402H16: tolerance: 64.33025.6DL
R2428 = R402H16: tolerance: 64.43R25.6DL; signal model: Graser_R2428
R2429 = R402H16: tolerance: 64.16005.6DL
R2446 = R402H16: tolerance: 64.33035.6DL
R2458 = R402H16: tolerance: 63.75034.1DL; signal model: Graser_R2458
R2468 = R402H16: tolerance: 64.16025.6DL
R2471 = R402H16: tolerance: 64.16515.6DL
R2505 = R402H16: tolerance: 64.45325.6DL
R2507 = R402H16: tolerance: 63.33034.1DL; signal model: Graser_R2507
R2611 = R402H16: tolerance: 64.95315.6DL
R2613 = R402H16: tolerance: 64.10525.6DL
R2714 = R402H16: tolerance: 64.22035.6DL
R2907 R2909 R3003 R3004 R3007 R3009 R3015 R3016 R4005 R4011 = R402H16: tolerance: 63.22334.1DL
R3101 = R402H16: tolerance: 64.24915.6DL
R3104 = R603H22: tolerance: 64.10045.55L
R3106 = R402H16: tolerance: 64.15025.6DL
R3201 R3202 R4014 R4016 = R402H16: tolerance: 64.24905.6DL
R3203 = 0R1210-4P-PAD: tolerance: ZZ.00PAD.I21; signal model: Graser_R3203
R3204 = R603H22: tolerance: 63.51133.15L
R3205 = 0R1210-4P-PAD: tolerance: ZZ.00PAD.I21; signal model: Graser_R3205
R3206 = 0R1210-4P-PAD: tolerance: ZZ.00PAD.I21; signal model: Graser_R3206
R3207 = 0R1210-4P-PAD: tolerance: ZZ.00PAD.I21; signal model: Graser_R3207
R3301 = 0R0402-PAD-1: tolerance: ZZ.00PAD.M11; signal model: Graser_R3301
R3302 = R402H16: tolerance: 64.62015.6DL
R3303 = 0R1210-4P-PAD: tolerance: ZZ.00PAD.I21; signal model: Graser_R3303
R3801 = 0R1210-4P-PAD: tolerance: ZZ.00PAD.I21; signal model: Graser_R3801
R3802 = 0R1210-4P-PAD: tolerance: ZZ.00PAD.I21; signal model: Graser_R3802
R3804 = 0R1210-4P-PAD: tolerance: ZZ.00PAD.I21; signal model: Graser_R3804
R3806 = 0R1210-4P-PAD: tolerance: ZZ.00PAD.I21; signal model: Graser_R3806
R3816 R4224 R4225 = R402H16: tolerance: 64.22025.6DL
R4221 R4223 = R402H16: tolerance: 64.30935.6DL
R6301 = R402H16: tolerance: 64.60425.6DL
R6302 R6315 = R402H16: tolerance: 64.75025.6DL
R6409 = R1206H28: tolerance: 63.22132.11L
R6413 = R1206H28: tolerance: 63.33132.11L
R6418 = R603H22: tolerance: 63.36134.15L
RJ45R1 = RUA1JA-KJKC-DE0-0R: tolerance: 022.10001.0E11
RN1901 = ARES8-CN24-MUH20: tolerance: 66.10336.08L
RN2001 = ARES2H18: tolerance: 66.10336.04L
RN2401-RN2403 = ARES8-CN24H20: tolerance: 66.82236.A8L
RN2404 RN2405 = SMD-ARES4H18: tolerance: 66.10236.04L
RN2501 = SMD-ARES4H18: tolerance: 66.33036.04L
RN2502 = SMD-ARES4H18: tolerance: 66.33036.04L; signal model: Graser_RN2502
RN5601 RN5901 = ARES2H16: tolerance: 66.22236.04L
SATA1 = LE18077-Z55D-4F: tolerance: 020.80129.0007
SATA2 = ABA-SAT-010-K04-U: tolerance: 20.81274.007
SATA3 = LE18077-Z55D-4F: tolerance: 020.80128.0007
SATAP1 = 733-71-06TB18: tolerance: 020.80826.0006
SB1 = BGA874M250240H60: tolerance: ZZ.CANON.001
SD1 = WK21921-151146-7H: tolerance: 062.10002.0341
SLOT1 = AAA-PCI-003-K45: tolerance: 20.50394.036
SLOT2 = 2EGH8211-27DL-4F: tolerance: 020.50008.0164
SSKT1 = SKT-SOIC8-1H211: tolerance: 62.10076.031
SSKT2 = SKT-SOIC16-153139H258: tolerance: 062.10029.0051
TC3201 TC3801 TC3901 = ECAP-100D6D3H493: tolerance: 09.2271D.L16
TP401-TP422 TP601 TP701 TP903 TP1501 TP1504-TP1509 TP2001-TP2003 TP2101 TP2102 TP2501 TP2502 TP9901-TP9906 = TPAD28: tolerance: ZZ.PAD28.XXX
TP3101-TP3103 TP9106 = TPAD30: tolerance: ZZ.PAD30.XXX
TR3201 = L125100-4PH24: tolerance: 068.24900.2001; signal model: Graser_TR3201
TR3202 = L125100-4PH24: tolerance: 068.24900.2001; signal model: Graser_TR3202
TR3801 = L125100-4PH24: tolerance: 068.24900.2001; signal model: Graser_TR3801
TR3802 = L125100-4PH24: tolerance: 068.24900.2001; signal model: Graser_TR3802
TR3901 = L125100-4PH24: tolerance: 068.24900.2001; signal model: Graser_TR3901
TR3902 = L125100-4PH24: tolerance: 068.24900.2001; signal model: Graser_TR3902
TR5601 = L125100-4PH24: tolerance: 068.24900.2001; signal model: Graser_TR5601
TR5602 = L125100-4PH24: tolerance: 068.24900.2001; signal model: Graser_TR5602
TR5603 = L125100-4PH24: tolerance: 068.24900.2001; signal model: Graser_TR5603
TR5604 = L125100-4PH24: tolerance: 068.24900.2001; signal model: Graser_TR5604
U2401 = PFPCC128-5H48: tolerance: 71.05553.00E
U2405 = SC70-5H44: tolerance: 073.7SZ32.000G
U2501 = SOIC8-1H86: tolerance: 072.25673.0001
U2502 = SOIC16-6H105: tolerance: 072.25673.0A01
U2601 = SOT-23-5H56: tolerance: 74.00709.A7F
U2602 U4009 U4010 = SC70-5H44: tolerance: 73.01G08.DHG
U2701 = LQFP48H63: tolerance: 071.03820.000G
U3101 = QFN32J4-G2D85H36: tolerance: 71.08111.U03
U3201 U3801 U3901 = SOT-23-5H58: tolerance: 074.00524.0B9F
U3301 = QFN24-G2D5H40-U: tolerance: 71.05170.003
U4201 = SON14J3020-G2610H32: tolerance: 074.02331.0A93
U4204 = PPAK-8P-3333-2H36: tolerance: 84.08103.037
U5602 = SOT23-2D4-312H48: tolerance: 074.02331.009B
U5901 = QFN32J4-G2D85H36: tolerance: 071.02166.0003
U6301 = SOT-23-5H51: tolerance: 74.09724.09F
U9101 = QFN32G5-G3D6H32: tolerance: 071.00750.0003
USB2R1 = SKT-USB12-157183: tolerance: 22.10321.W41
USB3F1 USB3F2 = SKT-USB11-138166: tolerance: 022.10005.0F41
VGA1 = VDS075W-D307-00A3F2B: tolerance: 020.20064.0015
X1801 = OSC-3225-4P-3H36: tolerance: 082.30006.0531
X1802 = SMD49-3215-0713H36: tolerance: 082.30003.0191
X3101 = SMD-OSC38H20: tolerance: 82.30020.I61

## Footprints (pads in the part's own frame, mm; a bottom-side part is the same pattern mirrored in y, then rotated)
0R0402-PAD-1
  custom 0.14x0.14 smd: 1(0,0.445) 2(0,-0.445)
0R0603-PAD-1-U
  custom 0.216x0.216 smd: 1(0,0.762) 2(0,-0.762)
0R0805-PAD-1-U
  rect 1.397x1.562 smd: 1(0,0.965)
  rect 1.397x1.569 smd: 2(0,-0.965)
0R1210-4P-PAD
  rect 1.041x0.457 smd: 1(-0.635,0.33) 2(-0.635,-0.33) 3(0.635,-0.33) 4(0.635,0.33)
2EGH8211-27DL-4F
  round 0.254 hole 2.362 unplated: (-73.15,0) (0,0)
  round 1.067 hole 0.711: A1(11.65,-1.25) A2(10.65,-3.25) A3(9.65,-1.25) A4(8.65,-3.25) A5(7.65,-1.25) A6(6.65,-3.25) A7(5.65,-1.25) A8(4.65,-3.25) A9(3.65,-1.25) A10(2.65,-3.25) A11(1.65,-1.25) A12(-1.35,-3.25) A13(-2.35,-1.25) A14(-3.35,-3.25) A15(-4.35,-1.25) A16(-5.35,-3.25) A17(-6.35,-1.25) A18(-7.35,-3.25) A19(-8.35,-1.25) A20(-9.35,-3.25) A21(-10.35,-1.25) A22(-11.35,-3.25) A23(-12.35,-1.25) A24(-13.35,-3.25) A25(-14.35,-1.25) A26(-15.35,-3.25) A27(-16.35,-1.25) A28(-17.35,-3.25) A29(-18.35,-1.25) A30(-19.35,-3.25) A31(-20.35,-1.25) A32(-21.35,-3.25) A33(-22.35,-1.25) A34(-23.35,-3.25) A35(-24.35,-1.25) A36(-25.35,-3.25) A37(-26.35,-1.25) A38(-27.35,-3.25) A39(-28.35,-1.25) A40(-29.35,-3.25) A41(-30.35,-1.25) A42(-31.35,-3.25) A43(-32.35,-1.25) A44(-33.35,-3.25) A45(-34.35,-1.25) A46(-35.35,-3.25) A47(-36.35,-1.25) A48(-37.35,-3.25) A49(-38.35,-1.25) A50(-39.35,-3.25) A51(-40.35,-1.25) A52(-41.35,-3.25) A53(-42.35,-1.25) A54(-43.35,-3.25) A55(-44.35,-1.25) A56(-45.35,-3.25) A57(-46.35,-1.25) A58(-47.35,-3.25) A59(-48.35,-1.25) A60(-49.35,-3.25) A61(-50.35,-1.25) A62(-51.35,-3.25) A63(-52.35,-1.25) A64(-53.35,-3.25) A65(-54.35,-1.25) A66(-55.35,-3.25) A67(-56.35,-1.25) A68(-57.35,-3.25) A69(-58.35,-1.25) A70(-59.35,-3.25) A71(-60.35,-1.25) A72(-61.35,-3.25) A73(-62.35,-1.25) A74(-63.35,-3.25) A75(-64.35,-1.25) A76(-65.35,-3.25) A77(-66.35,-1.25) A78(-67.35,-3.25) A79(-68.35,-1.25) A80(-69.35,-3.25) A81(-70.35,-1.25) A82(-71.35,-3.25) B1(11.65,1.25) B2(10.65,3.25) B3(9.65,1.25) B4(8.65,3.25) B5(7.65,1.25) B6(6.65,3.25) B7(5.65,1.25) B8(4.65,3.25) B9(3.65,1.25) B10(2.65,3.25) B11(1.65,1.25) B12(-1.35,3.25) B13(-2.35,1.25) B14(-3.35,3.25) B15(-4.35,1.25) B16(-5.35,3.25) B17(-6.35,1.25) B18(-7.35,3.25) B19(-8.35,1.25) B20(-9.35,3.25) B21(-10.35,1.25) B22(-11.35,3.25) B23(-12.35,1.25) B24(-13.35,3.25) B25(-14.35,1.25) B26(-15.35,3.25) B27(-16.35,1.25) B28(-17.35,3.25) B29(-18.35,1.25) B30(-19.35,3.25) B31(-20.35,1.25) B32(-21.35,3.25) B33(-22.35,1.25) B34(-23.35,3.25) B35(-24.35,1.25) B36(-25.35,3.25) B37(-26.35,1.25) B38(-27.35,3.25) B39(-28.35,1.25) B40(-29.35,3.25) B41(-30.35,1.25) B42(-31.35,3.25) B43(-32.35,1.25) B44(-33.35,3.25) B45(-34.35,1.25) B46(-35.35,3.25) B47(-36.35,1.25) B48(-37.35,3.25) B49(-38.35,1.25) B50(-39.35,3.25) B51(-40.35,1.25) B52(-41.35,3.25) B53(-42.35,1.25) B54(-43.35,3.25) B55(-44.35,1.25) B56(-45.35,3.25) B57(-46.35,1.25) B58(-47.35,3.25) B59(-48.35,1.25) B60(-49.35,3.25) B61(-50.35,1.25) B62(-51.35,3.25) B63(-52.35,1.25) B64(-53.35,3.25) B65(-54.35,1.25) B66(-55.35,3.25) B67(-56.35,1.25) B68(-57.35,3.25) B69(-58.35,1.25) B70(-59.35,3.25) B71(-60.35,1.25) B72(-61.35,3.25) B73(-62.35,1.25) B74(-63.35,3.25) B75(-64.35,1.25) B76(-65.35,3.25) B77(-66.35,1.25) B78(-67.35,3.25) B79(-68.35,1.25) B80(-69.35,3.25) B81(-70.35,1.25) B82(-71.35,3.25)
20-00950-1A01-A-U
  round 1.727 hole 1.321: 1(11.8,0) 2(-8.2,0)
21S-92-03GB16
  round 1.422 hole 1.016: 1(-2.54,-1.27) 2(-2.54,1.27) 3(0,-1.27) 4(0,1.27) 5(2.54,-1.27) 6(2.54,1.27)
733-71-06TB18
  round 0.254 hole 1.041 unplated: (-6,0) (6,0)
  round 1.676 hole 1.041: 1(3,-3.94) 2(0,-3.94) 3(-3,-3.94) 4(3,-0.94) 5(0,-0.94) 6(-3,-0.94)
87212-1400N
  rect 0.61x1.549 smd: 1(-6.5,-2.525) 2(-5.5,-2.525) 3(-4.5,-2.525) 4(-3.5,-2.525) 5(-2.5,-2.525) 6(-1.5,-2.525) 7(-0.5,-2.525) 8(0.5,-2.525) 9(1.5,-2.525) 10(2.5,-2.525) 11(3.5,-2.525) 12(4.5,-2.525) 13(5.5,-2.525) 14(6.5,-2.525)
  rect 1.194x1.803 smd: 15(-7.797,0) 16(7.797,0)
A2003WV0-2LX4PA-6T-Z-U
  round 1.27 hole 0.889: 1(-3,1) 2(-3,-1) 3(-1,1) 4(-1,-1) 5(1,1) 6(1,-1) 7(3,1)
  rect 0.025x0.025 smd: 8(3,-1)
AAA-PCI-003-K45
  round 0.254 hole 2.362 unplated: (0,0) (9.15,0)
  round 1.092 hole 0.737: A1(-11.65,1.25) A2(-10.65,3.25) A3(-9.65,1.25) A4(-8.65,3.25) A5(-7.65,1.25) A6(-6.65,3.25) A7(-5.65,1.25) A8(-4.65,3.25) A9(-3.65,1.25) A10(-2.65,3.25) A11(-1.65,1.25) A12(1.35,3.25) A13(2.35,1.25) A14(3.35,3.25) A15(4.35,1.25) A16(5.35,3.25) A17(6.35,1.25) A18(7.35,3.25) B1(-11.65,-1.25) B2(-10.65,-3.25) B3(-9.65,-1.25) B4(-8.65,-3.25) B5(-7.65,-1.25) B6(-6.65,-3.25) B7(-5.65,-1.25) B8(-4.65,-3.25) B9(-3.65,-1.25) B10(-2.65,-3.25) B11(-1.65,-1.25) B12(1.35,-3.25) B13(2.35,-1.25) B14(3.35,-3.25) B15(4.35,-1.25) B16(5.35,-3.25) B17(6.35,-1.25) B18(7.35,-3.25)
ABA-JAK-028-K03
  round 0.254 hole 2.311 unplated: (0,0)
  round 1.422 hole 1.016: 1(0,-3.8) 2(-5,-3.8) 3(-2.5,-3.8) 4(2.5,-3.8) 5(5,-3.8) 22(-3.75,-8.8) 23(-1.25,-8.8) 24(1.25,-8.8) 25(3.75,-8.8) 32(-3.75,-13.8) 33(-1.25,-13.8) 34(1.25,-13.8) 35(3.75,-13.8)
  round 2.718 hole 2.311: G1(6.04,0) G2(-6.04,0) G3(6.04,-11.3) G4(-6.04,-11.3)
ABA-SAT-010-K04-U
  round 1.118 hole 0.762: 1(-3.81,-0.5) 4(0,-0.5) 7(3.81,-0.5)
  oval 1.041x1.168 hole 0.762: 2(-2.54,0.5) 3(-1.27,0.5) 5(1.27,0.5) 6(2.54,0.5)
  round 1.778 hole 1.372: 8(-6.48,0) 9(6.48,0)
AH08847-A9L2-4M
  round 0.254 hole 2.464 unplated: (-74.55,0) (63.4,0)
  round 0.254 hole 2.464x1.219 unplated: (0,0)
  round 0.965 hole 0.66: 1(-68.9,-2.7) 2(-68.05,-1.1) 3(-67.2,-2.7) 4(-66.35,-1.1) 5(-65.5,-2.7) 6(-64.65,-1.1) 7(-63.8,-2.7) 8(-62.95,-1.1) 9(-62.1,-2.7) 10(-61.25,-1.1) 11(-60.4,-2.7) 12(-59.55,-1.1) 13(-58.7,-2.7) 14(-57.85,-1.1) 15(-57,-2.7) 16(-56.15,-1.1) 17(-55.3,-2.7) 18(-54.45,-1.1) 19(-53.6,-2.7) 20(-52.75,-1.1) 21(-51.9,-2.7) 22(-51.05,-1.1) 23(-50.2,-2.7) 24(-49.35,-1.1) 25(-48.5,-2.7) 26(-47.65,-1.1) 27(-46.8,-2.7) 28(-45.95,-1.1) 29(-45.1,-2.7) 30(-44.25,-1.1) 31(-43.4,-2.7) 32(-42.55,-1.1) 33(-41.7,-2.7) 34(-40.85,-1.1) 35(-40,-2.7) 36(-39.15,-1.1) 37(-38.3,-2.7) 38(-37.45,-1.1) 39(-36.6,-2.7) 40(-35.75,-1.1) 41(-34.9,-2.7) 42(-34.05,-1.1) 43(-33.2,-2.7) 44(-32.35,-1.1) 45(-31.5,-2.7) 46(-30.65,-1.1) 47(-29.8,-2.7) 48(-28.95,-1.1) 49(-28.1,-2.7) 50(-27.25,-1.1) 51(-26.4,-2.7) 52(-25.55,-1.1) 53(-24.7,-2.7) 54(-23.85,-1.1) 55(-23,-2.7) 56(-22.15,-1.1) 57(-21.3,-2.7) 58(-20.45,-1.1) 59(-19.6,-2.7) 60(-18.75,-1.1) 61(-17.9,-2.7) 62(-17.05,-1.1) 63(-16.2,-2.7) 64(-15.35,-1.1) 65(-14.5,-2.7) 66(-13.65,-1.1) 67(-12.8,-2.7) 68(-11.95,-1.1) 69(-11.1,-2.7) 70(-10.25,-1.1) 71(-9.4,-2.7) 72(-8.55,-1.1) 73(-7.7,-2.7) 74(-6.85,-1.1) 75(-6,-2.7) 76(-5.15,-1.1) 77(-4.3,-2.7) 78(1.65,-1.1) 79(2.5,-2.7) 80(3.35,-1.1) 81(4.2,-2.7) 82(5.05,-1.1) 83(5.9,-2.7) 84(6.75,-1.1) 85(7.6,-2.7) 86(8.45,-1.1) 87(9.3,-2.7) 88(10.15,-1.1) 89(11,-2.7) 90(11.85,-1.1) 91(12.7,-2.7) 92(13.55,-1.1) 93(14.4,-2.7) 94(15.25,-1.1) 95(16.1,-2.7) 96(16.95,-1.1) 97(17.8,-2.7) 98(18.65,-1.1) 99(19.5,-2.7) 100(20.35,-1.1) 101(21.2,-2.7) 102(22.05,-1.1) 103(22.9,-2.7) 104(23.75,-1.1) 105(24.6,-2.7) 106(25.45,-1.1) 107(26.3,-2.7) 108(27.15,-1.1) 109(28,-2.7) 110(28.85,-1.1) 111(29.7,-2.7) 112(30.55,-1.1) 113(31.4,-2.7) 114(32.25,-1.1) 115(33.1,-2.7) 116(33.95,-1.1) 117(34.8,-2.7) 118(35.65,-1.1) 119(36.5,-2.7) 120(37.35,-1.1) 121(38.2,-2.7) 122(39.05,-1.1) 123(39.9,-2.7) 124(40.75,-1.1) 125(41.6,-2.7) 126(42.45,-1.1) 127(43.3,-2.7) 128(44.15,-1.1) 129(45,-2.7) 130(45.85,-1.1) 131(46.7,-2.7) 132(47.55,-1.1) 133(48.4,-2.7) 134(49.25,-1.1) 135(50.1,-2.7) 136(50.95,-1.1) 137(51.8,-2.7) 138(52.65,-1.1) 139(53.5,-2.7) 140(54.35,-1.1) 141(55.2,-2.7) 142(56.05,-1.1) 143(56.9,-2.7) 144(57.75,-1.1) 145(-68.9,1.1) 146(-68.05,2.7) 147(-67.2,1.1) 148(-66.35,2.7) 149(-65.5,1.1) 150(-64.65,2.7) 151(-63.8,1.1) 152(-62.95,2.7) 153(-62.1,1.1) 154(-61.25,2.7) 155(-60.4,1.1) 156(-59.55,2.7) 157(-58.7,1.1) 158(-57.85,2.7) 159(-57,1.1) 160(-56.15,2.7) 161(-55.3,1.1) 162(-54.45,2.7) 163(-53.6,1.1) 164(-52.75,2.7) 165(-51.9,1.1) 166(-51.05,2.7) 167(-50.2,1.1) 168(-49.35,2.7) 169(-48.5,1.1) 170(-47.65,2.7) 171(-46.8,1.1) 172(-45.95,2.7) 173(-45.1,1.1) 174(-44.25,2.7) 175(-43.4,1.1) 176(-42.55,2.7) 177(-41.7,1.1) 178(-40.85,2.7) 179(-40,1.1) 180(-39.15,2.7) 181(-38.3,1.1) 182(-37.45,2.7) 183(-36.6,1.1) 184(-35.75,2.7) 185(-34.9,1.1) 186(-34.05,2.7) 187(-33.2,1.1) 188(-32.35,2.7) 189(-31.5,1.1) 190(-30.65,2.7) 191(-29.8,1.1) 192(-28.95,2.7) 193(-28.1,1.1) 194(-27.25,2.7) 195(-26.4,1.1) 196(-25.55,2.7) 197(-24.7,1.1) 198(-23.85,2.7) 199(-23,1.1) 200(-22.15,2.7) 201(-21.3,1.1) 202(-20.45,2.7) 203(-19.6,1.1) 204(-18.75,2.7) 205(-17.9,1.1) 206(-17.05,2.7) 207(-16.2,1.1) 208(-15.35,2.7) 209(-14.5,1.1) 210(-13.65,2.7) 211(-12.8,1.1) 212(-11.95,2.7) 213(-11.1,1.1) 214(-10.25,2.7) 215(-9.4,1.1) 216(-8.55,2.7) 217(-7.7,1.1) 218(-6.85,2.7) 219(-6,1.1) 220(-5.15,2.7) 221(-4.3,1.1) 222(1.65,2.7) 223(2.5,1.1) 224(3.35,2.7) 225(4.2,1.1) 226(5.05,2.7) 227(5.9,1.1) 228(6.75,2.7) 229(7.6,1.1) 230(8.45,2.7) 231(9.3,1.1) 232(10.15,2.7) 233(11,1.1) 234(11.85,2.7) 235(12.7,1.1) 236(13.55,2.7) 237(14.4,1.1) 238(15.25,2.7) 239(16.1,1.1) 240(16.95,2.7) 241(17.8,1.1) 242(18.65,2.7) 243(19.5,1.1) 244(20.35,2.7) 245(21.2,1.1) 246(22.05,2.7) 247(22.9,1.1) 248(23.75,2.7) 249(24.6,1.1) 250(25.45,2.7) 251(26.3,1.1) 252(27.15,2.7) 253(28,1.1) 254(28.85,2.7) 255(29.7,1.1) 256(30.55,2.7) 257(31.4,1.1) 258(32.25,2.7) 259(33.1,1.1) 260(33.95,2.7) 261(34.8,1.1) 262(35.65,2.7) 263(36.5,1.1) 264(37.35,2.7) 265(38.2,1.1) 266(39.05,2.7) 267(39.9,1.1) 268(40.75,2.7) 269(41.6,1.1) 270(42.45,2.7) 271(43.3,1.1) 272(44.15,2.7) 273(45,1.1) 274(45.85,2.7) 275(46.7,1.1) 276(47.55,2.7) 277(48.4,1.1) 278(49.25,2.7) 279(50.1,1.1) 280(50.95,2.7) 281(51.8,1.1) 282(52.65,2.7) 283(53.5,1.1) 284(54.35,2.7) 285(55.2,1.1) 286(56.05,2.7) 287(56.9,1.1) 288(57.75,2.7)
ARES2H16
  rect 0.356x0.66 smd: 1(-0.325,-0.599) 2(0.325,-0.599) 3(0.325,0.599) 4(-0.325,0.599)
ARES2H18
  rect 0.356x0.66 smd: 1(-0.325,-0.599) 2(0.325,-0.599) 3(0.325,0.599) 4(-0.325,0.599)
ARES8-CN24-MUH20
  rect 0.61x0.66 smd: 1(-0.9,-0.486) 4(0.9,-0.486) 5(0.9,0.486) 8(-0.9,0.486)
  rect 0.305x0.66 smd: 2(-0.25,-0.486) 3(0.25,-0.486) 6(0.25,0.486) 7(-0.25,0.486)
ARES8-CN24H20
  rect 0.61x0.66 smd: 1(-0.9,-0.486) 4(0.9,-0.486) 5(0.9,0.486) 8(-0.9,0.486)
  rect 0.305x0.66 smd: 2(-0.25,-0.486) 3(0.25,-0.486) 6(0.25,0.486) 7(-0.25,0.486)
AS0BC21-S40BE-7H
  round 0.254 hole 1.168 unplated: (-10,0)
  round 0.254 hole 1.651 unplated: (10,0)
  rect 0.305x1.549 smd: 1(-9.25,5.275) 2(-9,-2.275) 3(-8.75,5.275) 4(-8.5,-2.275) 5(-8.25,5.275) 6(-8,-2.275) 7(-7.75,5.275) 8(-7.5,-2.275) 9(-7.25,5.275) 10(-7,-2.275) 11(-6.75,5.275) 12(-6.5,-2.275) 13(-6.25,5.275) 14(-6,-2.275) 15(-5.75,5.275) 16(-5.5,-2.275) 17(-5.25,5.275) 18(-5,-2.275) 19(-4.75,5.275) 20(-4.5,-2.275) 21(-4.25,5.275) 22(-4,-2.275) 23(-3.75,5.275) 32(-1.5,-2.275) 33(-1.25,5.275) 34(-1,-2.275) 35(-0.75,5.275) 36(-0.5,-2.275) 37(-0.25,5.275) 38(0,-2.275) 39(0.25,5.275) 40(0.5,-2.275) 41(0.75,5.275) 42(1,-2.275) 43(1.25,5.275) 44(1.5,-2.275) 45(1.75,5.275) 46(2,-2.275) 47(2.25,5.275) 48(2.5,-2.275) 49(2.75,5.275) 50(3,-2.275) 51(3.25,5.275) 52(3.5,-2.275) 53(3.75,5.275) 54(4,-2.275) 55(4.25,5.275) 56(4.5,-2.275) 57(4.75,5.275) 58(5,-2.275) 59(5.25,5.275) 60(5.5,-2.275) 61(5.75,5.275) 62(6,-2.275) 63(6.25,5.275) 64(6.5,-2.275) 65(6.75,5.275) 66(7,-2.275) 67(7.25,5.275) 68(7.5,-2.275) 69(7.75,5.275) 70(8,-2.275) 71(8.25,5.275) 72(8.5,-2.275) 73(8.75,5.275) 74(9,-2.275) 75(9.25,5.275)
  rect 1.194x2.743 smd: 76(-10.35,4.5) 77(10.35,4.5)
AS0BC21-S85BM-7H
  round 0.254 hole 1.168 unplated: (-10,0)
  round 0.254 hole 1.651 unplated: (10,0)
  rect 0.305x1.549 smd: 1(-9.25,4.725) 2(-9,-1.725) 3(-8.75,4.725) 4(-8.5,-1.725) 5(-8.25,4.725) 6(-8,-1.725) 7(-7.75,4.725) 8(-7.5,-1.725) 9(-7.25,4.725) 10(-7,-1.725) 11(-6.75,4.725) 12(-6.5,-1.725) 13(-6.25,4.725) 14(-6,-1.725) 15(-5.75,4.725) 16(-5.5,-1.725) 17(-5.25,4.725) 18(-5,-1.725) 19(-4.75,4.725) 20(-4.5,-1.725) 21(-4.25,4.725) 22(-4,-1.725) 23(-3.75,4.725) 24(-3.5,-1.725) 25(-3.25,4.725) 26(-3,-1.725) 27(-2.75,4.725) 28(-2.5,-1.725) 29(-2.25,4.725) 30(-2,-1.725) 31(-1.75,4.725) 32(-1.5,-1.725) 33(-1.25,4.725) 34(-1,-1.725) 35(-0.75,4.725) 36(-0.5,-1.725) 37(-0.25,4.725) 38(0,-1.725) 39(0.25,4.725) 40(0.5,-1.725) 41(0.75,4.725) 42(1,-1.725) 43(1.25,4.725) 44(1.5,-1.725) 45(1.75,4.725) 46(2,-1.725) 47(2.25,4.725) 48(2.5,-1.725) 49(2.75,4.725) 50(3,-1.725) 51(3.25,4.725) 52(3.5,-1.725) 53(3.75,4.725) 54(4,-1.725) 55(4.25,4.725) 56(4.5,-1.725) 57(4.75,4.725) 58(5,-1.725) 67(7.25,4.725) 68(7.5,-1.725) 69(7.75,4.725) 70(8,-1.725) 71(8.25,4.725) 72(8.5,-1.725) 73(8.75,4.725) 74(9,-1.725) 75(9.25,4.725)
  rect 1.194x2.743 smd: 76(-10.35,4.5) 77(10.35,4.5)
BGA874M250240H60
  round 0.305 smd: A2(-11.46,11.314) A3(-10.959,11.314) A4(-10.459,11.314) A46(10.459,11.314) A47(10.959,11.314) A48(11.46,11.314) AA19(-3.099,1.549) AA20(-2.324,1.549) AA22(-1.549,1.549) AA23(-0.775,1.549) AA25(0,1.549) AA27(0.775,1.549) AA28(1.549,1.549) AA30(2.324,1.549) AA31(3.099,1.549) AB19(-3.099,0.775) AB20(-2.324,0.775) AB22(-1.549,0.775) AB23(-0.775,0.775) AB25(0,0.775) AB27(0.775,0.775) AB28(1.549,0.775) AB30(2.324,0.775) AB31(3.099,0.775) AC6(-9.374,0.579) AC7(-8.612,0.579) AC9(-7.85,0.579) AC11(-7.088,0.579) AC12(-6.326,0.579) AC14(-5.564,0.579) AC15(-4.802,0.579) AC17(-4.04,0.579) AC33(4.04,0.579) AC35(4.802,0.579) AC36(5.564,0.579) AC38(6.326,0.579) AC39(7.088,0.579) AC41(7.85,0.579) AC43(8.612,0.579) AC44(9.374,0.579) AD19(-3.099,0) AD20(-2.324,0) AD22(-1.549,0) AD23(-0.775,0) AD25(0,0) AD27(0.775,0) AD28(1.549,0) AD30(2.324,0) AD31(3.099,0) AE6(-9.374,-0.579) AE7(-8.612,-0.579) AE9(-7.85,-0.579) AE11(-7.088,-0.579) AE12(-6.326,-0.579) AE14(-5.564,-0.579) AE15(-4.802,-0.579) AE17(-4.04,-0.579) AE33(4.04,-0.579) AE35(4.802,-0.579) AE36(5.564,-0.579) AE38(6.326,-0.579) AE39(7.088,-0.579) AE41(7.85,-0.579) AE43(8.612,-0.579) AE44(9.374,-0.579) AF19(-3.099,-0.775) AF20(-2.324,-0.775) AF22(-1.549,-0.775) AF23(-0.775,-0.775) AF25(0,-0.775) AF27(0.775,-0.775) AF28(1.549,-0.775) AF30(2.324,-0.775) AF31(3.099,-0.775) AG19(-3.099,-1.549) AG20(-2.324,-1.549) AG22(-1.549,-1.549) AG23(-0.775,-1.549) AG25(0,-1.549) AG27(0.775,-1.549) AG28(1.549,-1.549) AG30(2.324,-1.549) AG31(3.099,-1.549) AH9(-7.919,-2.205) AH10(-7.18,-2.014) AH12(-6.402,-2.014) AH14(-5.564,-2.014) AH15(-4.789,-2.014) AH17(-4.027,-2.014) AH33(4.027,-2.014) AH35(4.789,-2.014) AH36(5.564,-2.014) AH38(6.402,-2.014) AH40(7.18,-2.014) AH41(7.919,-2.205) AJ6(-9.397,-2.586) AJ7(-8.658,-2.395) AJ19(-3.099,-2.324) AJ20(-2.324,-2.324) AJ22(-1.549,-2.324) AJ23(-0.775,-2.324) AJ25(0,-2.324) AJ27(0.775,-2.324) AJ28(1.549,-2.324) AJ30(2.324,-2.324) AJ31(3.099,-2.324) AJ43(8.658,-2.395) AJ44(9.397,-2.586) AK19(-3.099,-3.099) AK20(-2.324,-3.099) AK22(-1.549,-3.099) AK23(-0.775,-3.099) AK25(0,-3.099) AK27(0.775,-3.099) AK28(1.549,-3.099) AK30(2.324,-3.099) AK31(3.099,-3.099) AL9(-7.914,-3.495) AL10(-7.181,-3.259) AL12(-6.419,-3.259) AL13(-5.657,-3.259) AL15(-4.895,-3.259) AL17(-4.133,-3.259) AL21(-2.014,-3.578) AL24(-0.579,-3.591) AL26(0.579,-3.591) AL29(2.014,-3.578) AL33(4.133,-3.259) AL35(4.895,-3.259) AL37(5.657,-3.259) AL38(6.419,-3.259) AL40(7.181,-3.259) AL41(7.914,-3.495) AM7(-8.635,-3.843) AM18(-3.259,-3.683) AM32(3.259,-3.683) AM43(8.635,-3.843) AN6(-9.295,-4.224) AN10(-7.181,-4.656) AN12(-6.444,-4.351) AN13(-5.682,-4.351) AN15(-4.92,-4.351) AN16(-4.351,-4.394) AN18(-3.259,-4.394) AN21(-2.014,-4.289) AN24(-0.579,-4.302) AN26(0.579,-4.302) AN29(2.014,-4.289) AN32(3.259,-4.394) AN34(4.351,-4.394) AN35(4.92,-4.351) AN37(5.682,-4.351) AN38(6.444,-4.351) AN40(7.181,-4.656) AN44(9.295,-4.224) AP9(-7.914,-4.968) AP21(-2.014,-5.064) AP24(-0.579,-5.064) AP26(0.579,-5.064) AP29(2.014,-5.064) AP41(7.914,-4.968) AR8(-8.508,-5.469) AR12(-6.444,-5.443) AR13(-5.682,-5.443) AR15(-4.92,-5.443) AR16(-4.351,-5.182) AR18(-3.259,-5.156) AR32(3.259,-5.156) AR34(4.351,-5.182) AR35(4.92,-5.443) AR37(5.682,-5.443) AR38(6.444,-5.443) AR42(8.508,-5.469) AT6(-9.295,-5.659) AT10(-7.181,-5.773) AT16(-4.351,-5.944) AT18(-3.259,-5.918) AT21(-2.014,-5.902) AT24(-0.579,-5.826) AT26(0.579,-5.826) AT29(2.014,-5.902) AT32(3.259,-5.918) AT34(4.351,-5.944) AT40(7.181,-5.773) AT44(9.295,-5.659) AU9(-7.914,-6.416) AU24(-0.579,-6.588) AU26(0.579,-6.588) AU41(7.914,-6.416) AV6(-9.295,-7.094) AV7(-8.597,-6.764) AV11(-7.079,-6.975) AV13(-5.748,-6.757) AV16(-4.656,-6.719) AV18(-3.259,-6.68) AV21(-2.014,-6.679) AV29(2.014,-6.679) AV32(3.259,-6.68) AV34(4.656,-6.719) AV37(5.748,-6.757) AV39(7.079,-6.975) AV43(8.597,-6.764) AV44(9.295,-7.094) AW9(-7.824,-7.577) AW10(-7.262,-7.509) AW13(-6.01,-7.49) AW15(-4.892,-7.452) AW18(-3.495,-7.413) AW21(-2.205,-7.419) AW24(-0.579,-7.35) AW26(0.579,-7.35) AW29(2.205,-7.419) AW32(3.495,-7.413) AW35(4.892,-7.452) AW37(6.01,-7.49) AW40(7.262,-7.509) AW41(7.824,-7.577) AY8(-8.533,-7.898) AY42(8.533,-7.898) B1(-11.814,10.96) B2(-11.33,10.83) B3(-10.709,10.878) B47(10.709,10.878) B48(11.33,10.83) B49(11.814,10.96) BA6(-9.13,-8.203) BA12(-6.485,-8.135) BA14(-5.24,-8.135) BA17(-3.843,-8.135) BA20(-2.395,-8.158) BA24(-0.579,-8.112) BA26(0.579,-8.112) BA30(2.395,-8.158) BA33(3.843,-8.135) BA36(5.24,-8.135) BA38(6.485,-8.135) BA44(9.13,-8.203) BB6(-9.088,-8.706) BB7(-8.589,-9) BB9(-8.024,-8.774) BB11(-6.866,-8.795) BB14(-5.621,-8.795) BB16(-4.224,-8.795) BB20(-2.586,-8.897) BB24(-0.579,-8.874) BB26(0.579,-8.874) BB30(2.586,-8.897) BB34(4.224,-8.795) BB36(5.621,-8.795) BB39(6.866,-8.795) BB41(8.024,-8.774) BB43(8.589,-9) BB44(9.088,-8.706) BC5(-9.634,-9.254) BC45(9.634,-9.254) BD1(-11.814,-9.959) BD4(-10.474,-9.983) BD46(10.474,-9.983) BD49(11.814,-9.959) BE1(-11.814,-10.459) BE2(-11.373,-10.196) BE3(-10.86,-10.311) BE4(-10.391,-10.487) BE5(-9.965,-10.212) BE45(9.965,-10.212) BE46(10.391,-10.487) BE47(10.86,-10.311) BE48(11.373,-10.196) BE49(11.814,-10.459) BF1(-11.814,-10.96) BF2(-11.33,-10.83) BF3(-10.709,-10.878) BF47(10.709,-10.878) BF48(11.33,-10.83) BF49(11.814,-10.96) BG2(-11.46,-11.314) BG3(-10.959,-11.314) BG4(-10.459,-11.314) BG46(10.459,-11.314) BG47(10.959,-11.314) BG48(11.46,-11.314) C1(-11.814,10.459) C2(-11.373,10.196) C3(-10.86,10.311) C4(-10.391,10.487) C5(-9.965,10.212) C45(9.965,10.212) C46(10.391,10.487) C47(10.86,10.311) C48(11.373,10.196) C49(11.814,10.459) D1(-11.814,9.959) D4(-10.474,9.983) D46(10.474,9.983) D49(11.814,9.959) E5(-9.634,9.254) E45(9.634,9.254) F6(-9.088,8.706) F7(-8.589,9) F9(-8.024,8.774) F11(-6.866,8.795) F14(-5.621,8.795) F16(-4.224,8.795) F20(-2.586,8.897) F24(-0.579,8.874) F26(0.579,8.874) F30(2.586,8.897) F34(4.224,8.795) F36(5.621,8.795) F39(6.866,8.795) F41(8.024,8.774) F43(8.589,9) F44(9.088,8.706) G6(-9.13,8.203) G12(-6.485,8.135) G14(-5.24,8.135) G17(-3.843,8.135) G20(-2.395,8.158) G24(-0.579,8.112) G26(0.579,8.112) G30(2.395,8.158) G33(3.843,8.135) G36(5.24,8.135) G38(6.485,8.135) G44(9.13,8.203) H8(-8.533,7.898) H42(8.533,7.898) J9(-7.824,7.577) J10(-7.262,7.509) J13(-6.01,7.49) J15(-4.892,7.452) J18(-3.495,7.413) J21(-2.205,7.419) J24(-0.579,7.35) J26(0.579,7.35) J29(2.205,7.419) J32(3.495,7.413) J35(4.892,7.452) J37(6.01,7.49) J40(7.262,7.509) J41(7.824,7.577) K6(-9.295,7.094) K7(-8.597,6.764) K11(-7.079,6.975) K13(-5.748,6.757) K16(-4.656,6.719) K18(-3.259,6.68) K21(-2.014,6.679) K29(2.014,6.679) K32(3.259,6.68) K34(4.656,6.719) K37(5.748,6.757) K39(7.079,6.975) K43(8.597,6.764) K44(9.295,7.094) L9(-7.914,6.416) L24(-0.579,6.588) L26(0.579,6.588) L41(7.914,6.416) M6(-9.295,5.659) M10(-7.181,5.773) M16(-4.351,5.944) M18(-3.259,5.918) M21(-2.014,5.902) M24(-0.579,5.826) M26(0.579,5.826) M29(2.014,5.902) M32(3.259,5.918) M34(4.351,5.944) M40(7.181,5.773) M44(9.295,5.659) N8(-8.508,5.469) N12(-6.444,5.443) N13(-5.682,5.443) N15(-4.92,5.443) N16(-4.351,5.182) N18(-3.259,5.156) N32(3.259,5.156) N34(4.351,5.182) N35(4.92,5.443) N37(5.682,5.443) N38(6.444,5.443) N42(8.508,5.469) P9(-7.914,4.968) P21(-2.014,5.064) P24(-0.579,5.064) P26(0.579,5.064) P29(2.014,5.064) P41(7.914,4.968) R6(-9.295,4.224) R10(-7.181,4.656) R12(-6.444,4.351) R13(-5.682,4.351) R15(-4.92,4.351) R16(-4.351,4.394) R18(-3.259,4.394) R21(-2.014,4.289) R24(-0.579,4.302) R26(0.579,4.302) R29(2.014,4.289) R32(3.259,4.394) R34(4.351,4.394) R35(4.92,4.351) R37(5.682,4.351) R38(6.444,4.351) R40(7.181,4.656) R44(9.295,4.224) T7(-8.635,3.843) T17(-3.811,3.683) T18(-3.259,3.683) T32(3.259,3.683) T43(8.635,3.843) U9(-7.914,3.495) U10(-7.181,3.259) U12(-6.419,3.259) U13(-5.657,3.259) U15(-4.895,3.259) U17(-4.133,3.259) U21(-2.014,3.578) U24(-0.579,3.591) U26(0.579,3.591) U29(2.014,3.578) U33(4.133,3.259) U35(4.895,3.259) U37(5.657,3.259) U38(6.419,3.259) U40(7.181,3.259) U41(7.914,3.495) V19(-3.099,3.099) V20(-2.324,3.099) V22(-1.549,3.099) V23(-0.775,3.099) V25(0,3.099) V27(0.775,3.099) V28(1.549,3.099) V30(2.324,3.099) V31(3.099,3.099) W6(-9.397,2.586) W7(-8.658,2.395) W19(-3.099,2.324) W20(-2.324,2.324) W22(-1.549,2.324) W23(-0.775,2.324) W25(0,2.324) W27(0.775,2.324) W28(1.549,2.324) W30(2.324,2.324) W31(3.099,2.324) W43(8.658,2.395) W44(9.397,2.586) Y9(-7.919,2.205) Y10(-7.18,2.014) Y12(-6.402,2.014) Y14(-5.564,2.014) Y15(-4.789,2.014) Y17(-4.027,2.014) Y33(4.027,2.014) Y35(4.789,2.014) Y36(5.564,2.014) Y38(6.402,2.014) Y40(7.18,2.014) Y41(7.919,2.205)
  round 0.279 smd: A5(-9.958,11.314) A45(9.958,11.314) BC1(-11.814,-9.458) BC49(11.814,-9.458) BG5(-9.958,-11.314) BG45(9.958,-11.314) E1(-11.814,9.458) E49(11.814,9.458)
  oval 0.203x0.254 smd: A6(-9.399,11.314) A8(-8.294,11.314) A42(8.294,11.314) A44(9.399,11.314) BD8(-8.411,-9.813) BD12(-6.214,-9.813) BD17(-4.017,-9.813) BD21(-1.82,-9.813) BD29(1.82,-9.813) BD33(4.017,-9.813) BD38(6.214,-9.813) BD42(8.411,-9.813) BE9(-7.784,-10.186) BE10(-7.283,-10.059) BE14(-5.587,-10.186) BE15(-5.086,-10.059) BE18(-3.39,-10.186) BE19(-2.889,-10.059) BE23(-1.193,-10.186) BE24(-0.692,-10.059) BE26(0.692,-10.059) BE27(1.193,-10.186) BE31(2.889,-10.059) BE32(3.39,-10.186) BE35(5.086,-10.059) BE36(5.587,-10.186) BE40(7.283,-10.059) BE41(7.784,-10.186) BG6(-9.399,-11.314) BG8(-8.294,-11.314) BG42(8.294,-11.314) BG44(9.399,-11.314) C9(-7.784,10.186) C10(-7.283,10.059) C14(-5.587,10.186) C15(-5.086,10.059) C18(-3.39,10.186) C19(-2.889,10.059) C23(-1.193,10.186) C24(-0.692,10.059) C26(0.692,10.059) C27(1.193,10.186) C31(2.889,10.059) C32(3.39,10.186) C35(5.086,10.059) C36(5.587,10.186) C40(7.283,10.059) C41(7.784,10.186) D8(-8.411,9.813) D12(-6.214,9.813) D17(-4.017,9.813) D21(-1.82,9.813) D29(1.82,9.813) D33(4.017,9.813) D38(6.214,9.813) D42(8.411,9.813)
  oval 0.152x0.254 smd: A13(-6.072,11.314) A17(-3.875,11.314) A22(-1.678,11.314) A25(0,11.314) A28(1.678,11.314) A33(3.875,11.314) A37(6.072,11.314) B10(-7.123,10.603) B12(-6.265,10.816) B14(-5.587,10.687) B15(-4.926,10.603) B17(-4.068,10.816) B18(-3.39,10.687) B19(-2.729,10.603) B21(-1.871,10.816) B23(-1.193,10.687) B24(-0.532,10.603) B25(0,10.806) B26(0.532,10.603) B27(1.193,10.687) B29(1.871,10.816) B31(2.729,10.603) B32(3.39,10.687) B33(4.068,10.816) B35(4.926,10.603) B36(5.587,10.687) B38(6.265,10.816) B40(7.123,10.603) BE11(-6.76,-10.118) BE12(-6.295,-10.313) BE16(-4.563,-10.118) BE17(-4.098,-10.313) BE20(-2.366,-10.118) BE21(-1.901,-10.313) BE25(0,-10.298) BE29(1.901,-10.313) BE30(2.366,-10.118) BE33(4.098,-10.313) BE34(4.563,-10.118) BE38(6.295,-10.313) BE39(6.76,-10.118) BF10(-7.123,-10.603) BF12(-6.265,-10.816) BF14(-5.587,-10.687) BF15(-4.926,-10.603) BF17(-4.068,-10.816) BF18(-3.39,-10.687) BF19(-2.729,-10.603) BF21(-1.871,-10.816) BF23(-1.193,-10.687) BF24(-0.532,-10.603) BF25(0,-10.806) BF26(0.532,-10.603) BF27(1.193,-10.687) BF29(1.871,-10.816) BF31(2.729,-10.603) BF32(3.39,-10.687) BF33(4.068,-10.816) BF35(4.926,-10.603) BF36(5.587,-10.687) BF38(6.265,-10.816) BF40(7.123,-10.603) BG13(-6.072,-11.314) BG17(-3.875,-11.314) BG22(-1.678,-11.314) BG25(0,-11.314) BG28(1.678,-11.314) BG33(3.875,-11.314) BG37(6.072,-11.314) C11(-6.76,10.118) C12(-6.295,10.313) C16(-4.563,10.118) C17(-4.098,10.313) C20(-2.366,10.118) C21(-1.901,10.313) C25(0,10.298) C29(1.901,10.313) C30(2.366,10.118) C33(4.098,10.313) C34(4.563,10.118) C38(6.295,10.313) C39(6.76,10.118)
  oval 0.254x0.152 smd: AA1(-11.814,1.678) AA49(11.814,1.678) AB2(-11.187,1.193) AB48(11.187,1.193) AC2(-11.103,0.532) AC48(11.103,0.532) AD1(-11.814,0) AD2(-11.306,0) AD3(-10.798,0) AD47(10.798,0) AD48(11.306,0) AD49(11.814,0) AE2(-11.103,-0.532) AE48(11.103,-0.532) AF2(-11.187,-1.193) AF48(11.187,-1.193) AG1(-11.814,-1.678) AG49(11.814,-1.678) AH2(-11.316,-1.871) AH3(-10.813,-1.901) AH47(10.813,-1.901) AH48(11.316,-1.871) AJ3(-10.618,-2.366) AJ47(10.618,-2.366) AK2(-11.103,-2.729) AK48(11.103,-2.729) AL2(-11.187,-3.39) AL48(11.187,-3.39) AM1(-11.814,-3.875) AM2(-11.316,-4.068) AM3(-10.813,-4.098) AM47(10.813,-4.098) AM48(11.316,-4.068) AM49(11.814,-3.875) AN3(-10.618,-4.563) AN47(10.618,-4.563) AP2(-11.103,-4.926) AP48(11.103,-4.926) P2(-11.103,4.926) P48(11.103,4.926) R3(-10.618,4.563) R47(10.618,4.563) T1(-11.814,3.875) T2(-11.316,4.068) T3(-10.813,4.098) T47(10.813,4.098) T48(11.316,4.068) T49(11.814,3.875) U2(-11.187,3.39) U48(11.187,3.39) V2(-11.103,2.729) V48(11.103,2.729) W3(-10.618,2.366) W47(10.618,2.366) Y2(-11.316,1.871) Y3(-10.813,1.901) Y47(10.813,1.901) Y48(11.316,1.871)
  round 0.254 smd: AA5(-9.856,1.601) AA45(9.856,1.601) AC4(-10.06,0.579) AC46(10.06,0.579) AE4(-10.06,-0.579) AE46(10.06,-0.579) AG5(-9.856,-1.601) AG45(9.856,-1.601) AJ4(-10.098,-2.274) AJ46(10.098,-2.274) AK4(-10.06,-2.776) AK46(10.06,-2.776) AM5(-9.856,-3.799) AM45(9.856,-3.799) AN4(-10.098,-4.471) AN46(10.098,-4.471) AP4(-10.06,-4.973) AP46(10.06,-4.973) AT5(-9.856,-5.996) AT45(9.856,-5.996) AV4(-10.098,-6.669) AV46(10.098,-6.669) AW4(-10.06,-7.17) AW46(10.06,-7.17) B6(-9.397,10.811) B44(9.397,10.811) BA2(-11.316,-8.526) BA3(-10.809,-8.594) BA4(-10.304,-8.468) BA5(-9.856,-8.193) BA45(9.856,-8.193) BA46(10.304,-8.468) BA47(10.809,-8.594) BA48(11.316,-8.526) BB3(-11.318,-9.315) BB4(-10.825,-9.126) BB46(10.825,-9.126) BB47(11.318,-9.315) BC8(-8.193,-9.356) BC10(-7.17,-9.56) BC13(-5.996,-9.356) BC15(-4.973,-9.56) BC17(-3.799,-9.356) BC19(-2.776,-9.56) BC22(-1.601,-9.356) BC24(-0.579,-9.56) BC26(0.579,-9.56) BC28(1.601,-9.356) BC31(2.776,-9.56) BC33(3.799,-9.356) BC35(4.973,-9.56) BC37(5.996,-9.356) BC40(7.17,-9.56) BC42(8.193,-9.356) BD7(-8.914,-9.872) BD11(-6.669,-9.598) BD16(-4.471,-9.598) BD20(-2.274,-9.598) BD30(2.274,-9.598) BD34(4.471,-9.598) BD39(6.669,-9.598) BD43(8.914,-9.872) BE6(-9.091,-10.357) BE44(9.091,-10.357) BF6(-9.397,-10.811) BF44(9.397,-10.811) C6(-9.091,10.357) C44(9.091,10.357) D7(-8.914,9.872) D11(-6.669,9.598) D16(-4.471,9.598) D20(-2.274,9.598) D30(2.274,9.598) D34(4.471,9.598) D39(6.669,9.598) D43(8.914,9.872) E8(-8.193,9.356) E10(-7.17,9.56) E13(-5.996,9.356) E15(-4.973,9.56) E17(-3.799,9.356) E19(-2.776,9.56) E22(-1.601,9.356) E24(-0.579,9.56) E26(0.579,9.56) E28(1.601,9.356) E31(2.776,9.56) E33(3.799,9.356) E35(4.973,9.56) E37(5.996,9.356) E40(7.17,9.56) E42(8.193,9.356) F3(-11.318,9.315) F4(-10.825,9.126) F46(10.825,9.126) F47(11.318,9.315) G2(-11.316,8.526) G3(-10.809,8.594) G4(-10.304,8.468) G5(-9.856,8.193) G45(9.856,8.193) G46(10.304,8.468) G47(10.809,8.594) G48(11.316,8.526) J4(-10.06,7.17) J46(10.06,7.17) K4(-10.098,6.669) K46(10.098,6.669) M5(-9.856,5.996) M45(9.856,5.996) P4(-10.06,4.973) P46(10.06,4.973) R4(-10.098,4.471) R46(10.098,4.471) T5(-9.856,3.799) T45(9.856,3.799) V4(-10.06,2.776) V46(10.06,2.776) W4(-10.098,2.274) W46(10.098,2.274)
  oval 0.254x0.203 smd: AB3(-10.686,1.193) AB47(10.686,1.193) AC3(-10.559,0.692) AC47(10.559,0.692) AE3(-10.559,-0.692) AE47(10.559,-0.692) AF3(-10.686,-1.193) AF47(10.686,-1.193) AH4(-10.313,-1.82) AH46(10.313,-1.82) AK3(-10.559,-2.883) AK47(10.559,-2.883) AL3(-10.686,-3.39) AL47(10.686,-3.39) AM4(-10.313,-4.017) AM46(10.313,-4.017) AP3(-10.559,-5.08) AP47(10.559,-5.08) AR3(-10.686,-5.587) AR47(10.686,-5.587) AT1(-11.814,-6.097) AT49(11.814,-6.097) AU4(-10.313,-6.214) AU46(10.313,-6.214) AW3(-10.559,-7.277) AW47(10.559,-7.277) AY3(-10.686,-7.784) AY47(10.686,-7.784) BA1(-11.814,-8.32) BA49(11.814,-8.32) G1(-11.814,8.32) G49(11.814,8.32) H3(-10.686,7.784) H47(10.686,7.784) J3(-10.559,7.277) J47(10.559,7.277) L4(-10.313,6.214) L46(10.313,6.214) M1(-11.814,6.097) M49(11.814,6.097) N3(-10.686,5.587) N47(10.686,5.587) P3(-10.559,5.08) P47(10.559,5.08) T4(-10.313,4.017) T46(10.313,4.017) U3(-10.686,3.39) U47(10.686,3.39) V3(-10.559,2.883) V47(10.559,2.883) Y4(-10.313,1.82) Y46(10.313,1.82)
  oval 0.305x0.152 smd: AR2(-11.187,-5.587) AR48(11.187,-5.587) AU2(-11.316,-6.265) AU3(-10.813,-6.295) AU47(10.813,-6.295) AU48(11.316,-6.265) AV3(-10.618,-6.76) AV47(10.618,-6.76) AW2(-11.103,-7.123) AW48(11.103,-7.123) AY2(-11.187,-7.784) AY48(11.187,-7.784) H2(-11.187,7.784) H48(11.187,7.784) J2(-11.103,7.123) J48(11.103,7.123) K3(-10.618,6.76) K47(10.618,6.76) L2(-11.316,6.265) L3(-10.813,6.295) L47(10.813,6.295) L48(11.316,6.265) N2(-11.187,5.587) N48(11.187,5.587)
  oval 0.152x0.305 smd: B8(-8.462,10.816) B9(-7.784,10.687) B41(7.784,10.687) B42(8.462,10.816) BE8(-8.492,-10.313) BE42(8.492,-10.313) BF8(-8.462,-10.816) BF9(-7.784,-10.687) BF41(7.784,-10.687) BF42(8.462,-10.816) C8(-8.492,10.313) C42(8.492,10.313)
